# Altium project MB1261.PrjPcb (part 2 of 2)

## Sheet Peripherals.SchDoc: Peripherals
size A4; Author: P.A.; CompanyName: STMicroelectronics; Organization: Microcontrollers Division; Address1: 12, Rue Jules HOROWITZ; Address2: 38019 Grenoble; Address3: FRANCE; DocumentNumber: MB1261; Revision: B.01; SheetNumber: 7; SheetTotal: 15; Project: STM32L496G-DISCO
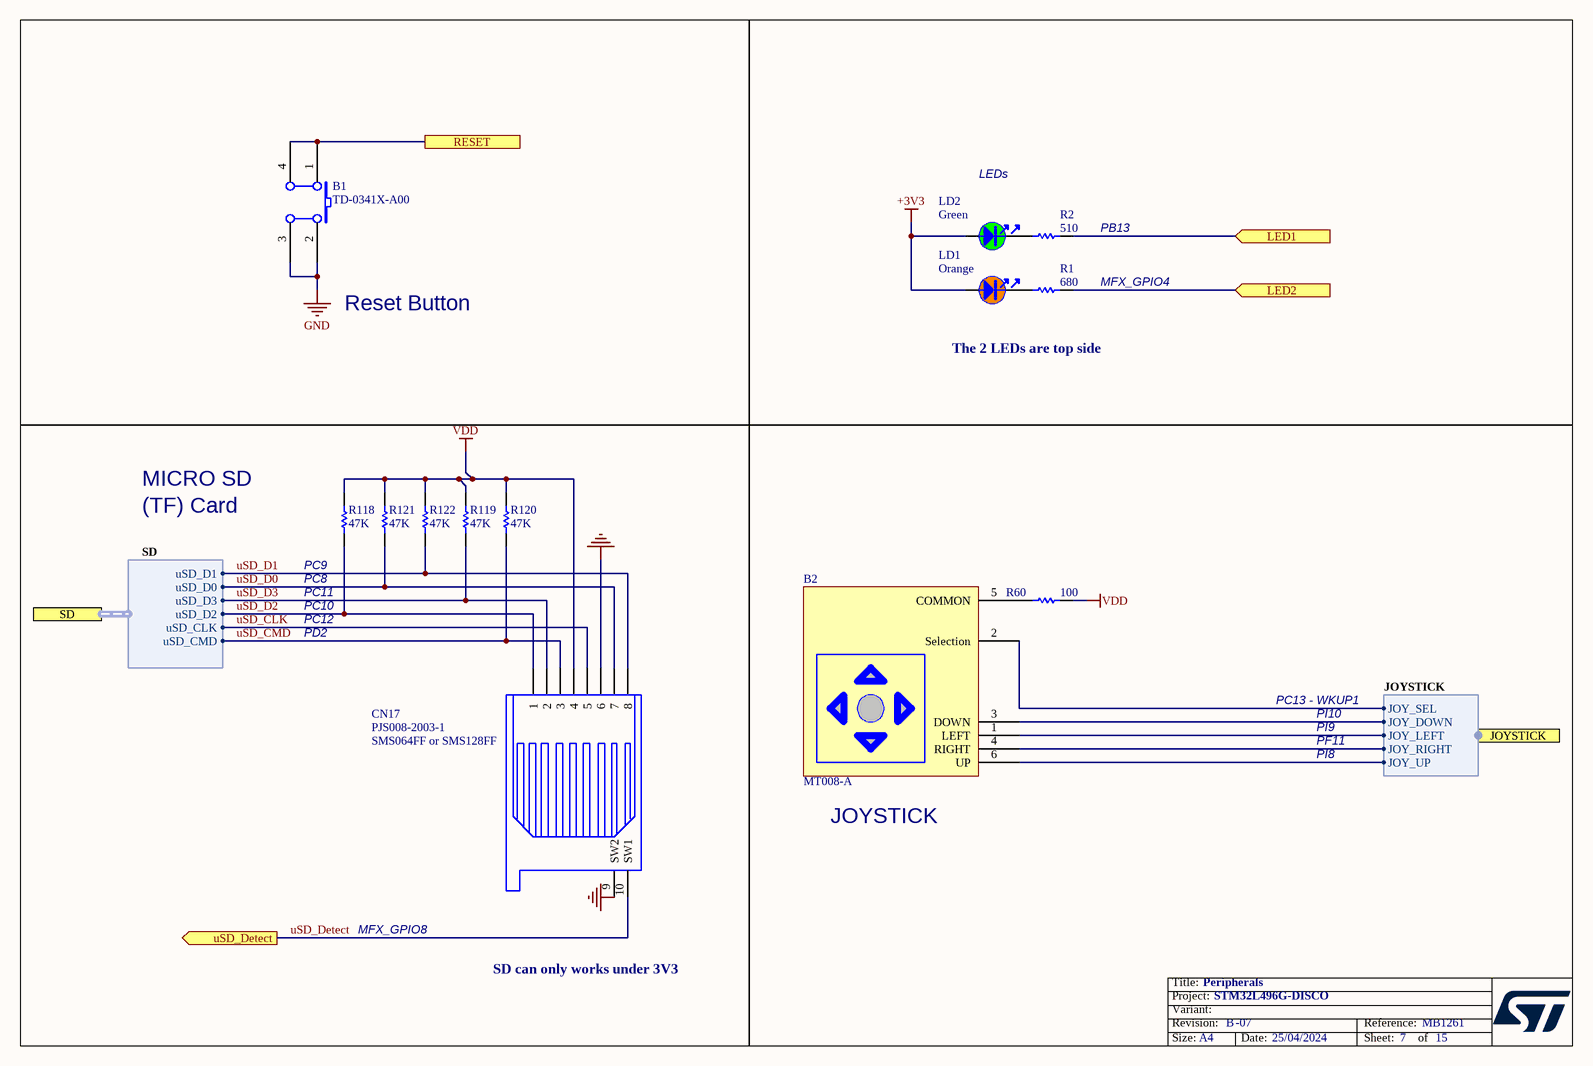
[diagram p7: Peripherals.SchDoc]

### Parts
B1  TD-0341X-A00  [PB10]
B2  MT008-A  [MT-008A]
CN17  PJS008-2003-1  [MSD_PJS008_]
LD1  value Orange  [LED_0603_ORANGE_H0P4]  (hidden comment: 19-217/S2C-AM2N2VY/3T)
LD2  value Green  [LED_0603_OSRAM_LG-Q396-PS-35_GREEN_1A2K_H0P4]  (hidden comment: LED_green)
R1  value 680  [0603R]  (hidden comment: RC0603FR-07680RL)
R2  value 510  [0603R]  (hidden comment: RC0603FR-07510RL)
R60  value 100  [0603R]  (hidden comment: RC0603JR-07100RL)
R118  47K  [0603R]
R119  47K  [0603R]
R120  47K  [0603R]
R121  47K  [0603R]
R122  47K  [0603R]

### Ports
JOYSTICK (harness JOYSTICK), LED1 (in), LED2 (in), RESET, SD (harness SD), uSD_Detect (out)

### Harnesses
SD: uSD_D0, uSD_CLK, uSD_D1, uSD_D2, uSD_D3, uSD_CMD
JOYSTICK: JOY_SEL, JOY_DOWN, JOY_LEFT, JOY_RIGHT, JOY_UP

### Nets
+3V3: LD1.1 LD2.1  [project net 3V3_OUT]
GND: B1.2(B0) B1.3(B1) CN17.6 CN17.9(SW2)
VDD: CN17.4 R60.1 R118.2 R119.2 R120.2 R121.2 R122.2
JOY_DOWN: B2.3(DOWN) ; port JOYSTICK.JOY_DOWN
JOY_LEFT: B2.1(LEFT) ; port JOYSTICK.JOY_LEFT
JOY_RIGHT: B2.4(RIGHT) ; port JOYSTICK.JOY_RIGHT
JOY_SEL: B2.2(Selection) ; port JOYSTICK.JOY_SEL
JOY_UP: B2.6(UP) ; port JOYSTICK.JOY_UP
LED1: R2.1 ; port LED1
NRST: B1.1(A0) B1.4(A1) ; port RESET
uSD_CLK: CN17.5 ; port SD.uSD_CLK
uSD_CMD: CN17.3 R120.1 ; port SD.uSD_CMD
uSD_D0: CN17.7 R121.1 ; port SD.uSD_D0
uSD_D1: CN17.8 R122.1 ; port SD.uSD_D1
uSD_D2: CN17.1 R118.1 ; port SD.uSD_D2
uSD_D3: CN17.2 R119.1 ; port SD.uSD_D3
uSD_Detect: CN17.10(SW1) ; port uSD_Detect
NetB2_5: B2.5(COMMON) R60.2
NetLD1_2: LD1.2 R1.2
NetLD2_2: LD2.2 R2.2
NetR1_1: R1.1 ; port LED2

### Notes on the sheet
- LEDs
- (near R2) PB13
- Reset Button
- MFX_GPIO4
- The 2 LEDs are top side
- MICRO SD
- (TF) Card
- (near R118) PC8
- (near R118) PC9
- PC11
- PC10
- PC12
- PD2
- PC13 - WKUP1
- PI9
- PI10
- (near CN17) SMS064FF or SMS128FF
- PF11
- PI8
- JOYSTICK
- MFX_GPIO8
- SD can only works under 3V3

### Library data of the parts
B1 = SW PUSHBUTTON: SE Push Button TD-0341 [RESET/Black]; Manuf_1: Chau-hua; Manuf_Part_1: CTSM-644N-V-T/R; Manuf_2: wealthmetal; Ordered by: Subcon; Assembly: with Back cap; Silkscreen: RESET; ECCN_US/EU: NA
B2 = MT-008A: Joystick; Manuf_1: XIEJIA; Ordered by: Subcon; Assembly: with button; ECCN_US/EU: NA
CN17 = SMS016AFA5E: Manuf_1: Yamaichi; Ordered by: Subcon; Silkscreen: uSD; ECCN_US/EU: NA
LD1 = MCD-02785: LED, Orange, 2V2, 5mA, 0603; Part_Type: Display; Part_Preference: Recommended; Manufacturer: EVERLIGHT; Manufacturer_Part_Number: 19-217/S2C-AM2N2VY/6T; Full_Alternate_Internal_Part_Number: MCD-00321; Component_Country_Of_Origin: China; ShowFields: YES; ID: 4897
LD2 = MCD-02901: LED, Green, 2V, 20mA, 0603; Part_Type: Display; Part_Preference: Recommended; Manufacturer: EVERLIGHT; Manufacturer_Part_Number: 19-217/G7C-AN1P2/6T; Partial_Alternate_Internal_Part_Number: MCD-02400; Component_Country_Of_Origin: China; ShowFields: YES; ID: 5017
R1 = res1: Resistor,680R,0603,1%,YAGEO; Ordered by: Subcon; ECCN_US/EU: NA
R2 = res1: Resistor,510R,0603,1%,YAGEO; Ordered by: Subcon; ECCN_US/EU: NA
R60 = res1: Resistor, 100 ,0603,1%,YAGEO; Ordered by: Subcon; ECCN_US/EU: NA
R118-R122 = res1: Resistor,47K,0603,1%,YAGEO; Manuf_Part_1: RC0603FR-0747KL; Ordered by: Subcon; ECCN_US/EU: NA

## Sheet Power.SchDoc: Power
size A4; Author: P.A.; CompanyName: STMicroelectronics; Organization: Microcontrollers Division; Address1: 12, Rue Jules HOROWITZ; Address2: 38019 Grenoble; Address3: FRANCE; DocumentNumber: MB1261; Revision: B.01; SheetNumber: 3; SheetTotal: 15; Project: STM32L496G-DISCO
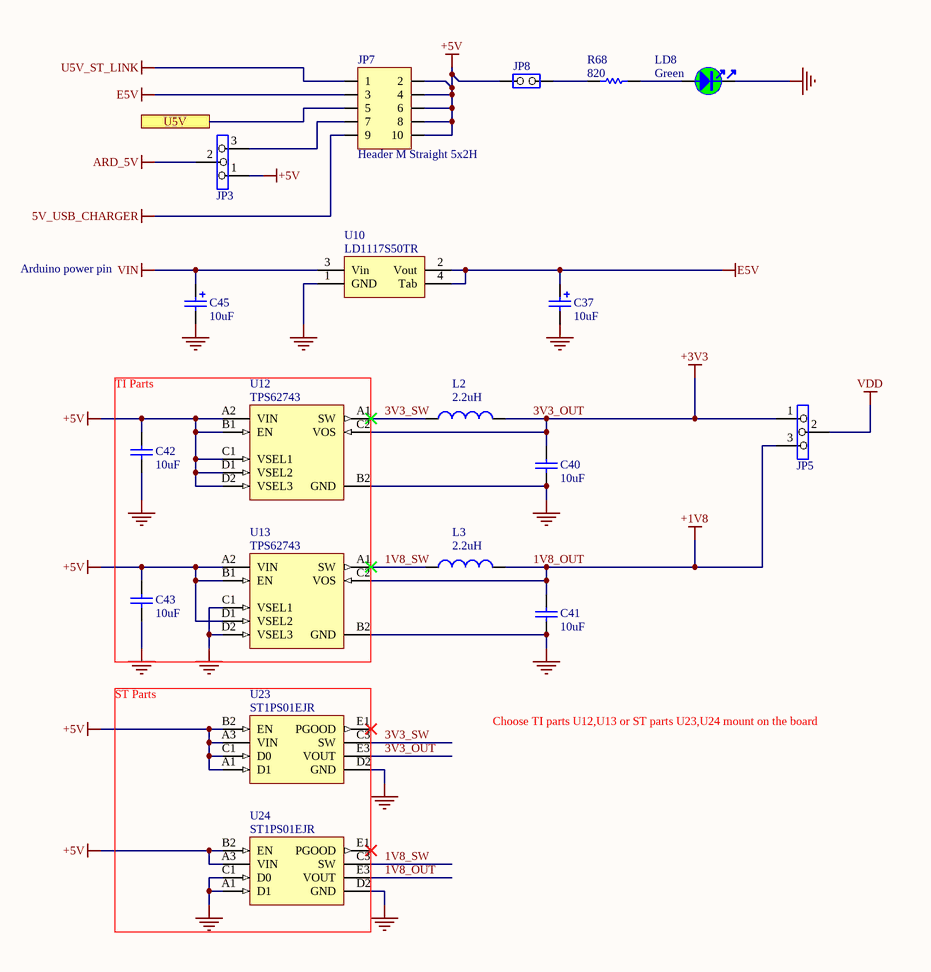
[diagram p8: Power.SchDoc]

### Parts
C37  value 10uF  [TAN-A]  (hidden comment: TAJA106K016R)
C40  value 10uF  [C0402]  (hidden comment: GRM155R60J106ME11)
C41  value 10uF  [C0402]  (hidden comment: GRM155R60J106ME11)
C42  value 10uF  [C0402]  (hidden comment: GRM155R60J106ME11)
C43  value 10uF  [C0402]  (hidden comment: GRM155R60J106ME11)
C45  value 10uF  [TAN-B]  (hidden comment: TAJB106K025RNJ)
JP3  3 PIN Jumper  [SIP3]  (value not drawn)
JP5  3 PIN Jumper  [SIP3]  (value not drawn)
JP7  Header M Straight 5x2H  [HDR_2X5_2R54]
JP8  2 PIN Jumper  [SIP2]  (value not drawn)
L2  2.2uH  [L1008_L0805_CPT]
L3  2.2uH  [L1008_L0805_CPT]
LD8  value Green  [LED_0603_OSRAM_LG-Q396-PS-35_GREEN_1A2K_H0P4]  (hidden comment: 19-213SY6C/S530-E2/TR8LED)
R68  820  [0603R]
U10  LD1117S50TR  [SOT-223]
U12  TPS62743  [BGA8_0R4_0R9X1R6]
U13  TPS62743  [BGA8_0R4_0R9X1R6]
U23  ST1PS01EJR  [BGA8_0R312-0R25_1R11X1R41]
U24  ST1PS01EJR  [BGA8_0R312-0R25_1R11X1R41]

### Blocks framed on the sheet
TI Parts: C42 C43 U12 U13
ST Parts: U23 U24

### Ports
U5V

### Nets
1V8_OUT: C41.1 JP5.3 L3.2 U13.C2(VOS) U24.E3(VOUT)  [also labelled +1V8]
3V3_OUT: C40.1 JP5.1 L2.2 U12.C2(VOS) U23.E3(VOUT)  [also labelled +3V3]
5V_USB_CHARGER: JP7.9
+5V: C42.1 C43.1 JP3.1 JP7.2 JP7.4 JP7.6 JP7.8 JP7.10 JP8.1(COMMON) U12.A2(VIN) U12.B1(EN) U12.C1(VSEL1) U12.D1(VSEL2) U12.D2(VSEL3) U13.A2(VIN) U13.B1(EN) U13.D1(VSEL2) U23.A1(D1) U23.A3(VIN) U23.B2(EN) U23.C1(D0) U24.A3(VIN) U24.B2(EN)
ARD_5V: JP3.2
E5V: C37.1 JP7.3 U10.2(Vout) U10.4(Tab)
GND: C37.2 C40.2 C41.2 C42.2 C43.2 C45.2 LD8.2 U10.1(GND) U12.B2(GND) U13.B2(GND) U13.C1(VSEL1) U13.D2(VSEL3) U23.D2(GND) U24.A1(D1) U24.C1(D0) U24.D2(GND)
U5V_ST_LINK: JP7.1
VDD: JP5.2
VIN: C45.1 U10.3(Vin)
1V8_SW: L3.1 U13.A1(SW) U24.C3(SW)
3V3_SW: L2.1 U12.A1(SW) U23.C3(SW)
USB_OTGFS_VBUS: JP7.5 ; port U5V
NetJP3_3: JP3.3 JP7.7
NetJP8_2: JP8.2(NO) R68.2
NetLD8_1: LD8.1 R68.1

Not connected (* = marked no-connect by the designer): U23 E1(PGOOD)*; U24 E1(PGOOD)*

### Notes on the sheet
- Arduino power pin
- Choose TI parts U12,U13 or ST parts U23,U24 mount on the board

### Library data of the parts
C37 = Cap Pol1: TAN Capacitor,10uF,10%,16V,A Type,AVX; Ordered by: Subcon; ECCN_US/EU: NA
C40-C43 = MCD-01532: Capacitor, MLCC, 10uF, 10V, X5R, +/-20%, 0402, T=0.5mm; Part_Preference: Recommended; Manufacturer: MURATA; Manufacturer_Part_Number: GRM155R61A106ME11; Component_Country_Of_Origin: Japan°°; ShowFields: YES; ID: 3632
C45 = Cap Pol1: Tan Capacitor,10uF,10%,25V,Tan-B,TAJB106K025RNJ; Manuf_1: AVX; Ordered by: Subcon; ECCN_US/EU: NA
JP3 JP5 = Jumper3: Manuf_1: lyconn; Manuf_Part_1: 313103S111116; Ordered by: Subcon; Silkscreen: +3V3: pins 1&2 +1V8: pins 2&3; ECCN_US/EU: NA
JP7 = Header 5X2M: Pin Header male,2.54mm,2*5,L=11.6,180,1U,DIP; Manuf_1: Lyconn; Ordered by: Subcon
JP8 = JP2: Manuf_1: lyconn; Manuf_Part_1: 313102S111116; Ordered by: Subcon; Assembly: with jumper; ECCN_US/EU: NA
L2 L3 = Inductor: Manuf_1: TDK; Manuf_Part_1: VLS252010HBX-2R2M-1; Ordered by: Subcon; ECCN_US/EU: NA
LD8 = MCD-02901: as LD2 on sheet Peripherals
R68 = res1: Resistor; Manuf_1: YAGEO; Manuf_Part_1: RC0603FR-07820RL; Ordered by: Subcon; ECCN_US/EU: NA
U10 = LD1117S18TR: Adjustable and fixed low drop positive voltage regulator; Ordered by: STM
U12 U13 = TPS62743: High Efficiency Buck Converter; Manuf_1: TI; Ordered by: Subcon
U23 = ST1PS01EJR: 400mA NanoQuiescent Step Down converter; Manuf_1: STM
U24 = ST1PS01EJR: 400mA NanoQuiescent Step Down converter; Ordered by: STM

## Sheet PSRAM.SchDoc: PSRAM
size A4; Author: P.A.; CompanyName: STMicroelectronics; Organization: Microcontrollers Division; Address1: 12, Rue Jules HOROWITZ; Address2: 38019 Grenoble; Address3: FRANCE; DocumentNumber: MB1261; Revision: B.01; SheetNumber: 12; SheetTotal: 15; Project: STM32L496G-DISCO
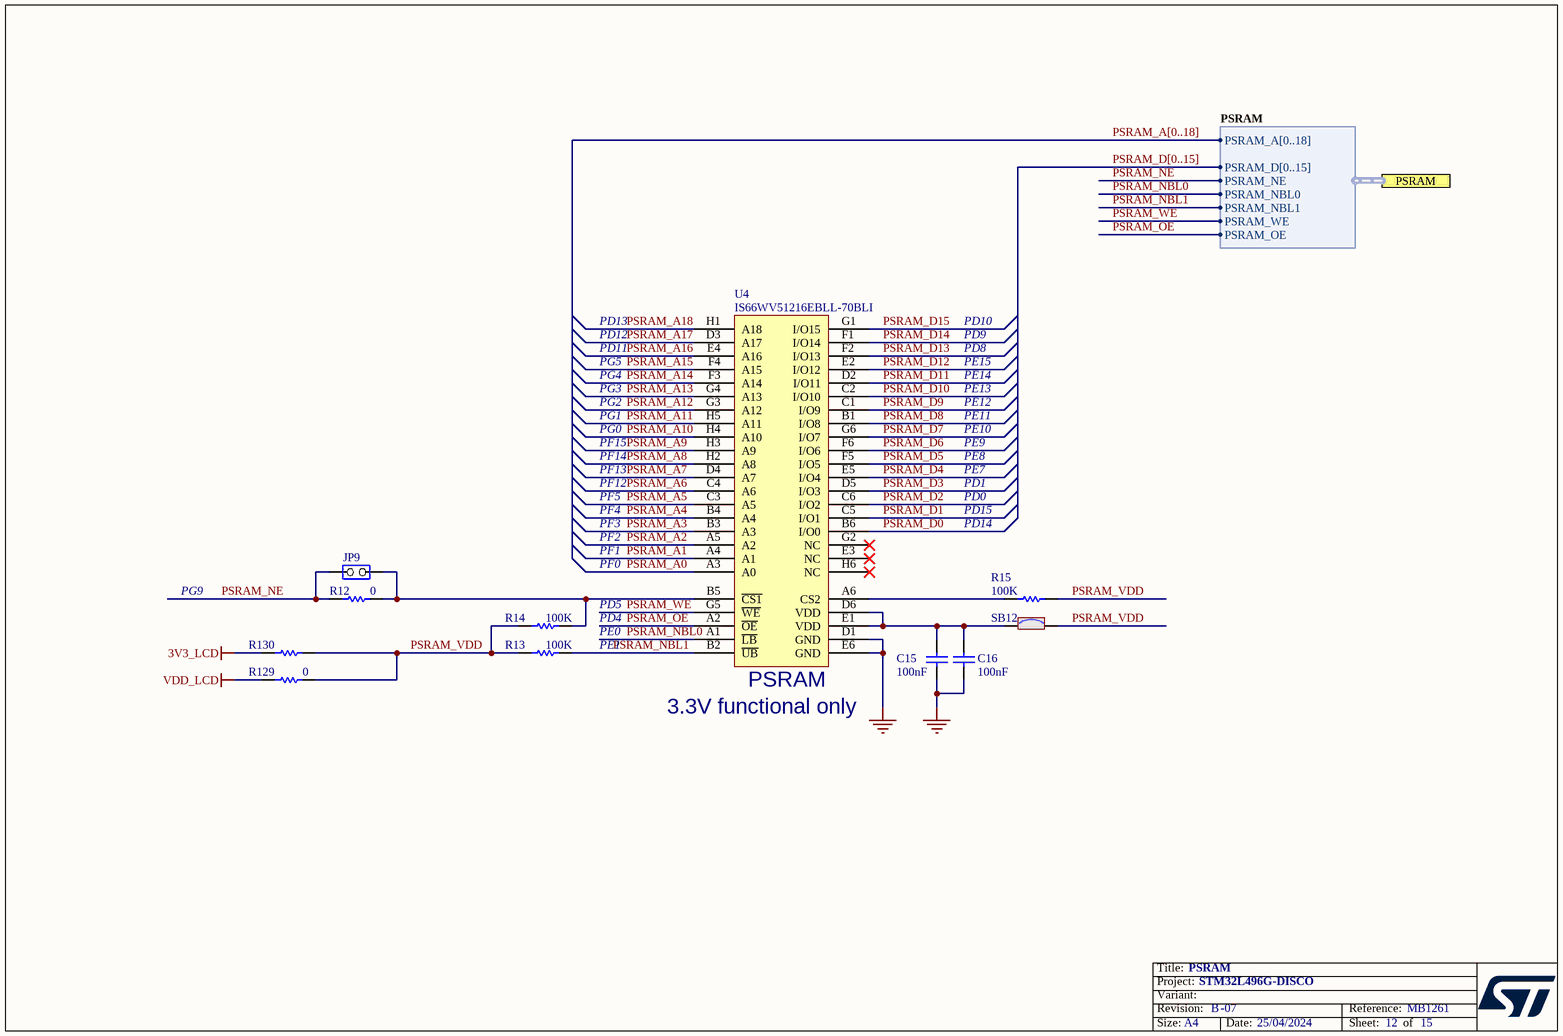
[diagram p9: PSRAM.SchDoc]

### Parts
C15  value 100nF  [0603C]  (hidden comment: CC0603KRX7R7BB104)
C16  value 100nF  [0603C]  (hidden comment: CC0603KRX7R7BB104)
JP9  2 PIN Jumper  [SIP2]  (value not drawn)
R12  0  [0603R]
R13  value 100K  [0603R]  (hidden comment: RC0603FR-07100KL)
R14  value 100K  [0603R]  (hidden comment: RC0603FR-07100KL)
R15  value 100K  [0603R]  (hidden comment: RC0603FR-07100KL)
R129  value 0  [0603R]  (hidden comment: RC0603JR-070RL)
R130  (no value)  [0603R]
SB12  Solder Bridge ON  [SB_0603]  (value not drawn)
U4  IS66WV51216EBLL-70BLI  [FBGA48_0R75_6X8]

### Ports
PSRAM (harness PSRAM)

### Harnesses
PSRAM: PSRAM_A[0..18], PSRAM_NE, PSRAM_NBL0, PSRAM_WE, PSRAM_OE, PSRAM_D[0..15], PSRAM_NBL1

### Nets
3V3_LCD: R130.2
GND: C15.2 C16.2 U4.D1(GND) U4.E6(GND)
VDD_LCD: R129.2
PSRAM_A0: U4.A3(A0)
PSRAM_A1: U4.A4(A1)
PSRAM_A2: U4.A5(A2)
PSRAM_A3: U4.B3(A3)
PSRAM_A4: U4.B4(A4)
PSRAM_A5: U4.C3(A5)
PSRAM_A6: U4.C4(A6)
PSRAM_A7: U4.D4(A7)
PSRAM_A8: U4.H2(A8)
PSRAM_A9: U4.H3(A9)
PSRAM_A10: U4.H4(A10)
PSRAM_A11: U4.H5(A11)
PSRAM_A12: U4.G3(A12)
PSRAM_A13: U4.G4(A13)
PSRAM_A14: U4.F3(A14)
PSRAM_A15: U4.F4(A15)
PSRAM_A16: U4.E4(A16)
PSRAM_A17: U4.D3(A17)
PSRAM_A18: U4.H1(A18)  [project net LCD_RS]
PSRAM_D0: U4.B6(I/O0)  [project net D0]
PSRAM_D1: U4.C5(I/O1)  [project net D1]
PSRAM_D2: U4.C6(I/O2)  [project net D2]
PSRAM_D3: U4.D5(I/O3)  [project net D3]
PSRAM_D4: U4.E5(I/O4)  [project net D4]
PSRAM_D5: U4.F5(I/O5)  [project net D5]
PSRAM_D6: U4.F6(I/O6)  [project net D6]
PSRAM_D7: U4.G6(I/O7)  [project net D7]
PSRAM_D8: U4.B1(I/O8)  [project net D8]
PSRAM_D9: U4.C1(I/O9)  [project net D9]
PSRAM_D10: U4.C2(I/O10)  [project net D10]
PSRAM_D11: U4.D2(I/O11)  [project net D11]
PSRAM_D12: U4.E2(I/O12)  [project net D12]
PSRAM_D13: U4.F2(I/O13)  [project net D13]
PSRAM_D14: U4.F1(I/O14)  [project net D14]
PSRAM_D15: U4.G1(I/O15)  [project net D15]
PSRAM_NBL0: U4.A1(~{LB}) ; port PSRAM.PSRAM_NBL0
PSRAM_NBL1: R13.1 U4.B2(~{UB}) ; port PSRAM.PSRAM_NBL1
PSRAM_NE: JP9.1(COMMON) R12.2 ; port PSRAM.PSRAM_NE
PSRAM_OE: U4.A2(~{OE}) ; port PSRAM.PSRAM_OE  [project net LCD_OE]
PSRAM_VDD: R13.2 R14.2 R15.1 R129.1 R130.1 SB12.2
PSRAM_WE: U4.G5(~{WE}) ; port PSRAM.PSRAM_WE  [project net LCD_WE]
NetC15_1: C15.1 C16.1 SB12.1 U4.D6(VDD) U4.E1(VDD)
NetJP9_2: JP9.2(NO) R12.1 R14.1 U4.B5(~{CS1})
NetR15_2: R15.2 U4.A6(CS2)

Not connected (* = marked no-connect by the designer): U4 E3(NC)* G2(NC)* H6(NC)*

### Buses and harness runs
bus PSRAM_A[0..18]
bus PSRAM_D[0..15]

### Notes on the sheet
- PD11
- PD12
- PD13
- PG4
- PG5
- PE14
- PE15
- PD8
- PD9
- PD10
- PF15
- PG0
- PG1
- PG2
- PG3
- PE9
- PE10
- PE11
- PE12
- PE13
- PF4
- PF5
- PF12
- PF13
- PF14
- PD15
- PD0
- PD1
- PE7
- PE8
- PF0
- PF1
- PF2
- PF3
- PD14
- PG9
- PD5
- PD4
- PE0
- PE1
- 3.3V functional only
- (near U4) PSRAM

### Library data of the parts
C15 C16 = Cap: Capacitor,100nF,10%,16V,X7R,0603,YAGEO; Ordered by: Subcon
JP9 = JP2: as JP8 on sheet Power
R12 = res1: Resistor, 0 ,0603,1%,YAGEO; Manuf_Part_1: RC0603JR-070RL; Ordered by: Subcon; ECCN_US/EU: NA
R13-R15 = res1: Resistor,100K,0603,1%,YAGEO; Ordered by: Subcon; ECCN_US/EU: NA
R129 = res1: Resistor, 0 ,0603,1%,YAGEO; Ordered by: Subcon; ECCN_US/EU: NA
R130 = res1: Resistor, 0 ,0603,1%,YAGEO; Manuf_Part_1: RC0603JR-070RL; Value: 0; Ordered by: Subcon; ECCN_US/EU: NA
SB12 = SB_ON: Manuf_1: YAGEO; Manuf_Part_1: RC0603JR-070RL; Solder: YES; Ordered By: Subcon
U4 = IS66WV51216EBLL-70BLI: 8M Bit static RAMs organized as 512K words by  16 bits.; Manuf_1: ISSI; Ordered by: STM

## Sheet QSPI.SchDoc: QSPI Flash
size A4; Author: P.A.; CompanyName: STMicroelectronics; Organization: Microcontrollers Division; Address1: 12, Rue Jules HOROWITZ; Address2: 38019 Grenoble; Address3: FRANCE; DocumentNumber: MB1261; Revision: B.01; SheetNumber: 6; SheetTotal: 15; Project: STM32L496G-DISCO
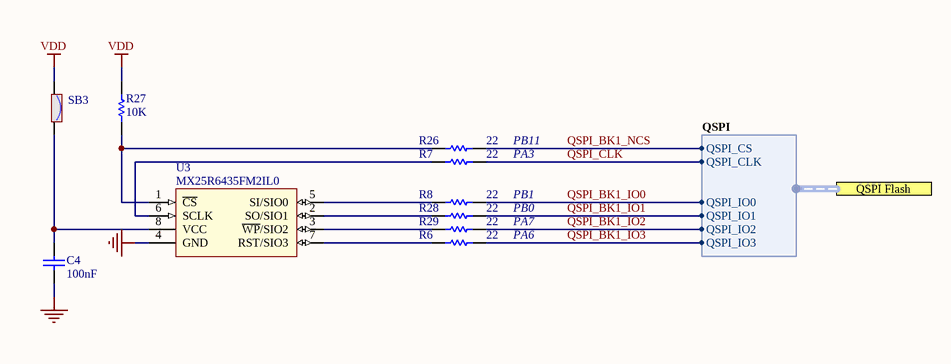
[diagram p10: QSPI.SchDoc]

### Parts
C4  value 100nF  [0603C]  (hidden comment: CC0603KRX7R7BB104)
R6  value 22  [0603R]  (hidden comment: RC0603JR-0722RL)
R7  value 22  [0603R]  (hidden comment: RC0603JR-0722RL)
R8  value 22  [0603R]  (hidden comment: RC0603JR-0722RL)
R26  value 22  [0603R]  (hidden comment: RC0603JR-0722RL)
R27  value 10K  [0603R]  (hidden comment: RC0603FR-0710KL)
R28  value 22  [0603R]  (hidden comment: RC0603JR-0722RL)
R29  value 22  [0603R]  (hidden comment: RC0603JR-0722RL)
SB3  Solder Bridge ON  [SB_0603]  (value not drawn)
U3  MX25R6435FM2IL0  [SOIC8_1R27_5R28X7R9]

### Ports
QSPI Flash (harness QSPI)

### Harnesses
QSPI: QSPI_IO1, QSPI_IO0, QSPI_CLK, QSPI_CS, QSPI_IO2, QSPI_IO3

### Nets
GND: C4.2 U3.4(GND)
VDD: R27.2 SB3.1
QSPI_BK1_IO0: R8.1 ; port QSPI Flash.QSPI_IO0
QSPI_BK1_IO1: R28.1 ; port QSPI Flash.QSPI_IO1
QSPI_BK1_IO2: R29.1 ; port QSPI Flash.QSPI_IO2
QSPI_BK1_IO3: R6.1 ; port QSPI Flash.QSPI_IO3
QSPI_BK1_NCS: R26.1 ; port QSPI Flash.QSPI_CS
QSPI_CLK: R7.1 ; port QSPI Flash.QSPI_CLK
NetC4_1: C4.1 SB3.2 U3.8(VCC)
NetR6_2: R6.2 U3.7(RST/SIO3)
NetR7_2: R7.2 U3.6(SCLK)
NetR8_2: R8.2 U3.5(SI/SIO0)
NetR26_2: R26.2 R27.1 U3.1(~{CS})
NetR28_2: R28.2 U3.2(SO/SIO1)
NetR29_2: R29.2 U3.3(~{WP}/SIO2)

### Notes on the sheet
- PB11
- PA3
- PB0
- PB1
- PA6
- PA7

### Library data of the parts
C4 = Cap: as C15 on sheet PSRAM
R6-R8 R26 R28 R29 = res1: Resistor, 22 ,0603,1%,YAGEO; Ordered by: Subcon; ECCN_US/EU: NA
R27 = res1: Resistor,10K,0603,1%,YAGEO; Ordered by: Subcon; ECCN_US/EU: NA
SB3 = SB_ON: as SB12 on sheet PSRAM
U3 = MX25R6435FM2IL0: Ultra Low Power 64M-BIT CMOS MXSMIO FLASH MEMORY; Manuf_1: MXIC; Ordered by: Subcon

## Sheet ST_LINK_V2-1_2.SCHDOC: ST-LINK/V2-1
size A3; Author: P.A.; CompanyName: STMicroelectronics; Organization: Microcontrollers Division; Address1: 12, Rue Jules HOROWITZ; Address2: 38019 Grenoble; Address3: FRANCE; DocumentNumber: MB1261; Revision: B.01; SheetNumber: 5; SheetTotal: 15; Project: STM32L496G-DISCO
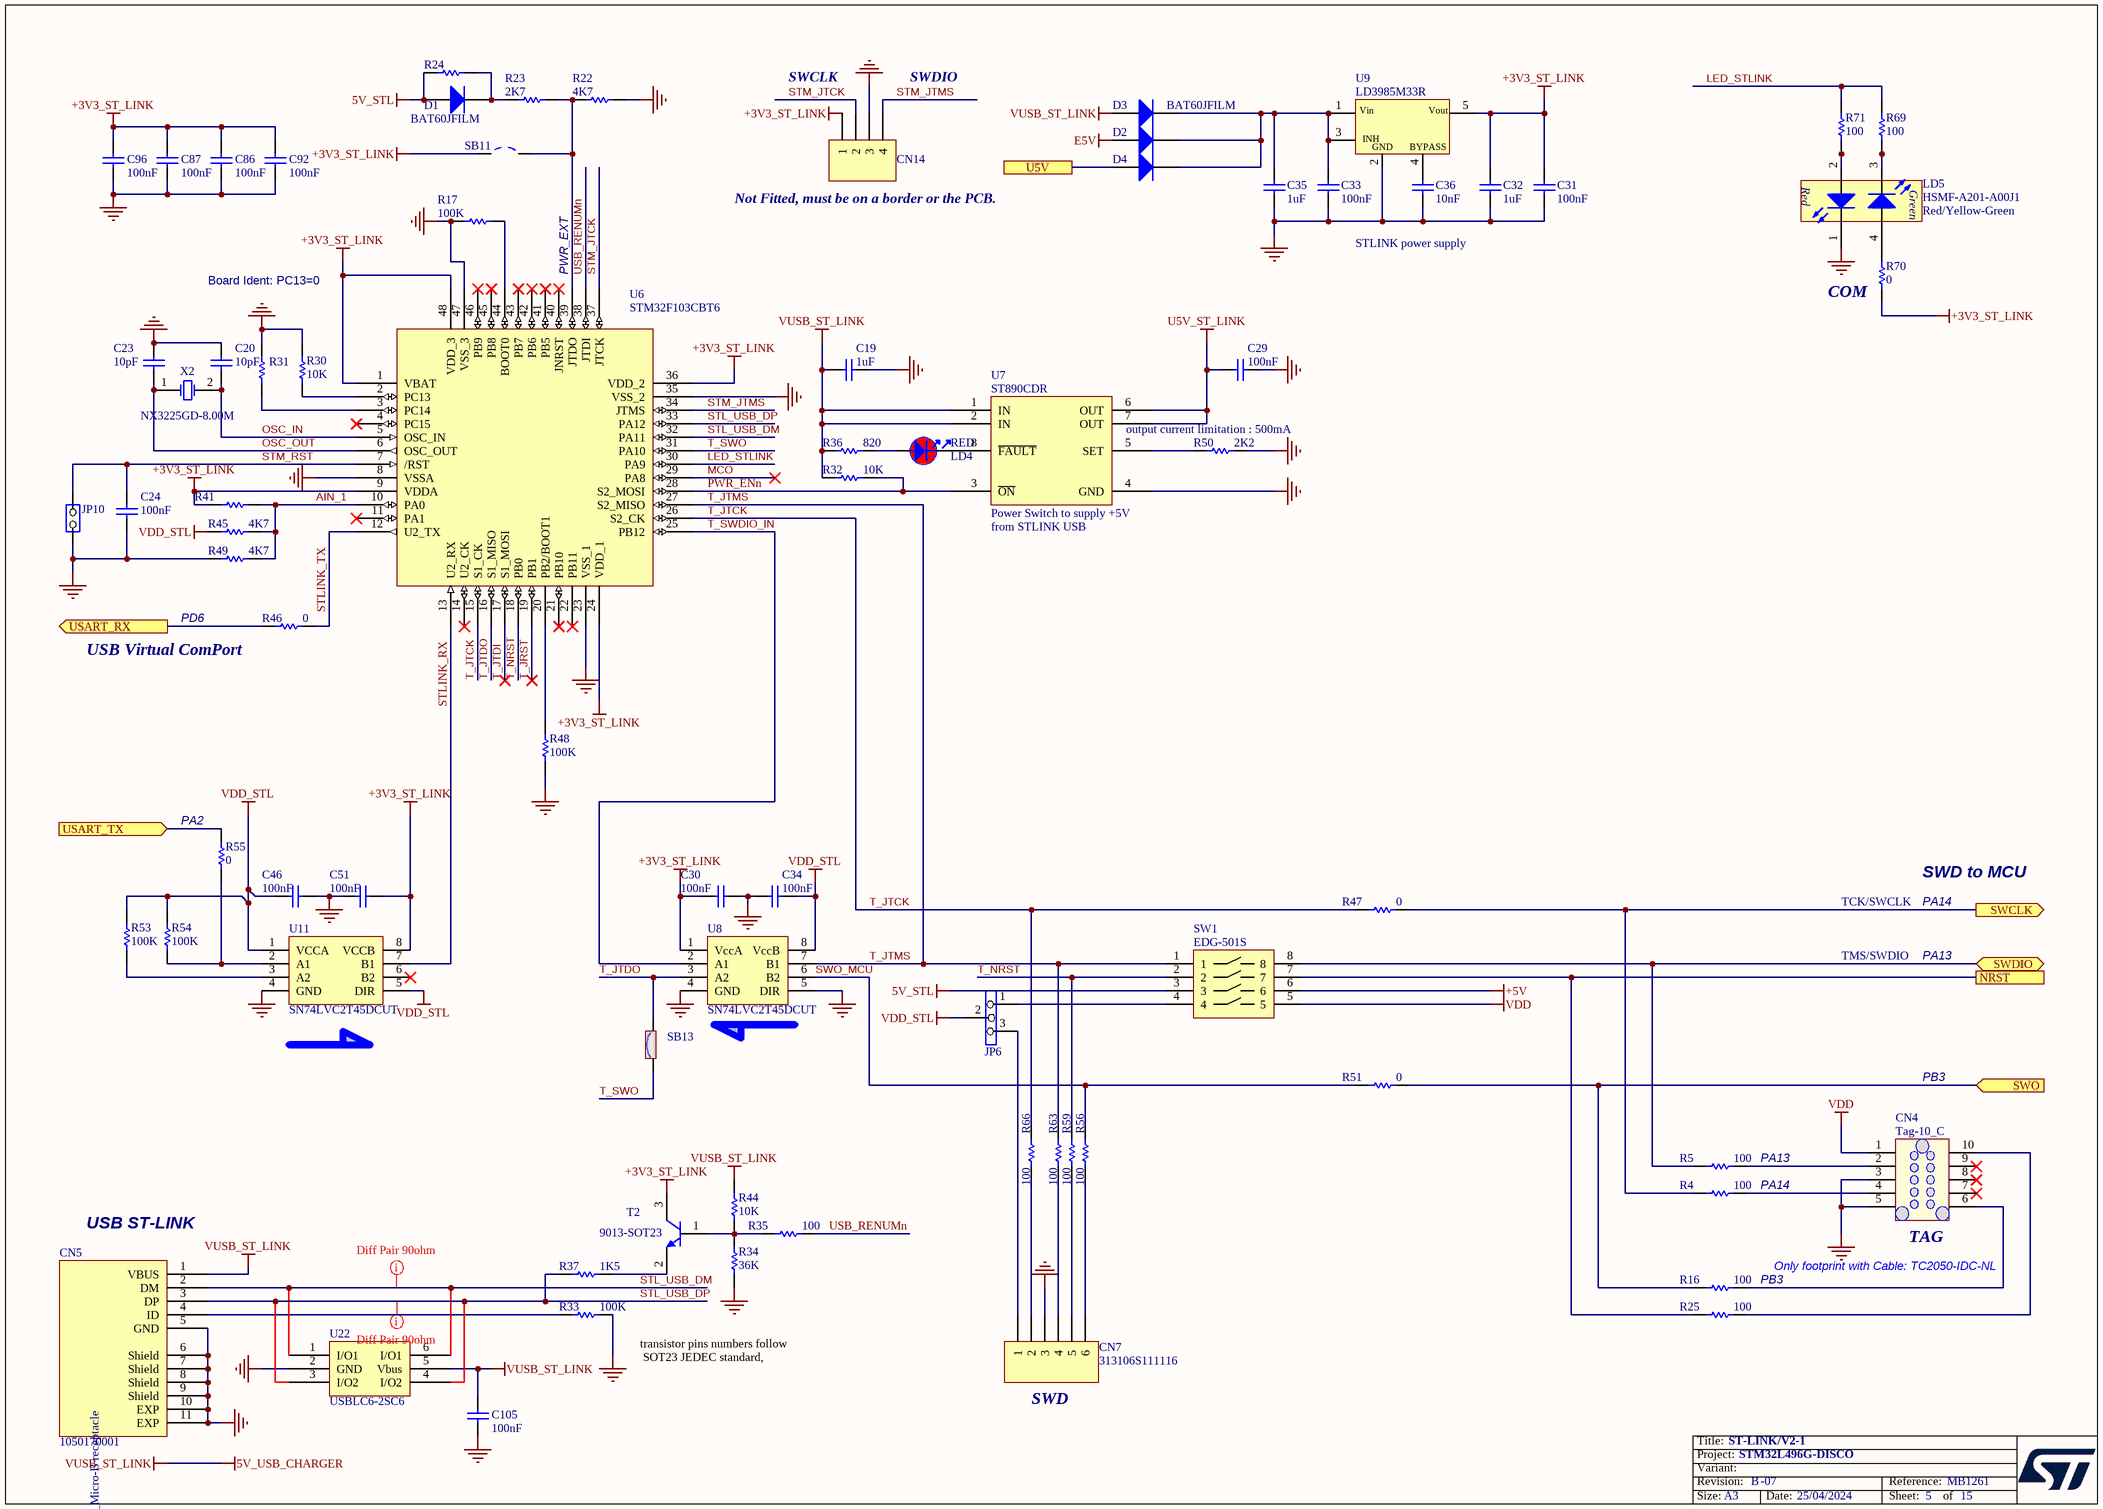
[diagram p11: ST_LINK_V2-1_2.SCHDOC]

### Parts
C19  value 1uF  [0603C]  (hidden comment: CC0603KRX5R7BB105)
C20  value 10pF  [0603C]  (hidden comment: CC0603JRNPO9BN100)
C23  value 10pF  [0603C]  (hidden comment: CC0603JRNPO9BN100)
C24  value 100nF  [0603C]  (hidden comment: CC0603KRX7R7BB104)
C29  value 100nF  [0603C]  (hidden comment: CC0603KRX7R7BB104)
C30  value 100nF  [0603C]  (hidden comment: CC0603KRX7R7BB104)
C31  value 100nF  [0603C]  (hidden comment: CC0603KRX7R7BB104)
C32  value 1uF  [0603C]  (hidden comment: CC0603KRX5R7BB105)
C33  value 100nF  [0603C]  (hidden comment: CC0603KRX7R7BB104)
C34  value 100nF  [0603C]  (hidden comment: CC0603KRX7R7BB104)
C35  value 1uF  [0603C]  (hidden comment: CC0603KRX5R7BB105)
C36  value 10nF  [C0603]  (hidden comment: CC0603KRX7R9BB103)
C46  value 100nF  [0603C]  (hidden comment: CC0603KRX7R7BB104)
C51  value 100nF  [0603C]  (hidden comment: CC0603KRX7R7BB104)
C86  value 100nF  [0603C]  (hidden comment: CC0603KRX7R7BB104)
C87  value 100nF  [0603C]  (hidden comment: CC0603KRX7R7BB104)
C92  value 100nF  [0603C]  (hidden comment: CC0603KRX7R7BB104)
C96  value 100nF  [0603C]  (hidden comment: CC0603KRX7R7BB104)
C105  value 100nF  [0603C]  (hidden comment: CC0603KRX7R7BB104)
CN4  Tag-10_C  [TC2050-IDC-NL]
CN5  1050170001  [MICRO_USB_B_105017]
CN7  313106S111116  [HDR_1X6_2R54_W]
CN14  (no value)  [HDR_1X4_2R54]
D1  BAT60JFILM  [SOD-323]
D2  (no value)  [SOD-323]
D3  BAT60JFILM  [SOD-323]
D4  (no value)  [SOD-323]
JP6  3 PIN Jumper  [SIP3]  (value not drawn)
JP10  (no value)  [SIP2]
LD4  value RED  [LED_0603_VISHAY_VLMS1300-GS08_RED_1A2K_H0P8]  (hidden comment: 19-217/R6C-AL1M2VY/3T)
LD5  HSMF-A201-A00J1  value Red/Yellow-Green  [LED_BI-GR_HSMF-A201-A00J1]
R4  value 100  [0603R]  (hidden comment: RC0603JR-07100RL)
R5  value 100  [0603R]  (hidden comment: RC0603JR-07100RL)
R16  value 100  [0603R]  (hidden comment: RC0603JR-07100RL)
R17  value 100K  [0603R]  (hidden comment: RC0603FR-07100KL)
R22  value 4K7  [0603R]  (hidden comment: RC0603FR-074K7L)
R23  value 2K7  [0603R]  (hidden comment: RC0603FR-072K7L)
R24  (no value)  [0603R]
R25  value 100  [0603R]  (hidden comment: RC0603JR-07100RL)
R30  value 10K  [0603R]  (hidden comment: RC0603FR-0710KL)
R31  (no value)  [0603R]
R32  value 10K  [0603R]  (hidden comment: RC0603FR-0710KL)
R33  value 100K  [0603R]  (hidden comment: RC0603FR-07100KL)
R34  value 36K  [0603R]  (hidden comment: RC0603FR-0736KL)
R35  value 100  [0603R]  (hidden comment: RC0603JR-07100RL)
R36  820  [0603R]
R37  value 1K5  [0603R]  (hidden comment: RC0603FR-071K5L)
R41  (no value)  [0603R]
R44  value 10K  [0603R]  (hidden comment: RC0603FR-0710KL)
R45  value 4K7  [0603R]  (hidden comment: RC0603FR-074K7L)
R46  value 0  [0603R]  (hidden comment: RC0603JR-070RL)
R47  value 0  [0603R]  (hidden comment: RC0603JR-070RL)
R48  value 100K  [0603R]  (hidden comment: RC0603FR-07100KL)
R49  value 4K7  [0603R]  (hidden comment: RC0603FR-074K7L)
R50  value 2K2  [0603R]  (hidden comment: RC0603FR-072K2L)
R51  value 0  [0603R]  (hidden comment: RC0603JR-070RL)
R53  value 100K  [0603R]  (hidden comment: RC0603FR-07100KL)
R54  value 100K  [0603R]  (hidden comment: RC0603FR-07100KL)
R55  value 0  [0603R]  (hidden comment: RC0603JR-070RL)
R56  value 100  [0603R]  (hidden comment: RC0603JR-07100RL)
R59  value 100  [0603R]  (hidden comment: RC0603JR-07100RL)
R63  value 100  [0603R]  (hidden comment: RC0603JR-07100RL)
R66  value 100  [0603R]  (hidden comment: RC0603JR-07100RL)
R69  value 100  [0603R]  (hidden comment: RC0603JR-07100RL)
R70  value 0  [0603R]  (hidden comment: RC0603JR-070RL)
R71  value 100  [0603R]  (hidden comment: RC0603JR-07100RL)
SB11  Solder Bridge OFF  [SB_0603]  (value not drawn)
SB13  Solder Bridge ON  [SB_0603]  (value not drawn)
SW1  EDG-501S  [SW1_11R7X9R7-12R2X9R65-HDR_CPT]
T2  9013-SOT23  [SOT-23]
U6  STM32F103CBT6  [LQFP48_0R5_9X9]
U7  ST890CDR  [SOIC8_1R27_4R9X6]
U8  SN74LVC2T45DCUT  [USOP8_0R5_2X3R1]
U9  LD3985M33R  [SOT23-5]
U11  SN74LVC2T45DCUT  [USOP8_0R5_2X3R1]
U22  USBLC6-2SC6  [SOT23-6L]
X2  NX3225GD-8.00M  [XTAL_2SM_3R2X2R5]

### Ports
NRST, SWCLK (out), SWDIO (bidir), SWO (in), U5V, USART_RX (out), USART_TX (in)

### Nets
5V_STL: D1.1(A) R24.2 SW1.3
5V_USB_CHARGER: C19.2 C105.1 CN5.1(VBUS) D3.1(A) R32.1 R36.2 R44.1 U7.1(IN) U7.2(IN) U22.5(Vbus)  [also labelled VUSB_ST_LINK]
+3V3_ST_LINK: C30.2 C31.1 C32.1 C51.2 C86.1 C87.1 C92.1 C96.1 CN14.1 R41.1 R70.1 SB11.1 T2.3(C) U6.1(VBAT) U6.9(VDDA) U6.24(VDD_1) U6.36(VDD_2) U6.48(VDD_3) U8.1(VccA) U9.5(Vout) U11.8(VCCB)
+5V: SW1.6
E5V: D2.1(A)
GND: C19.1 C20.1 C23.1 C24.2 C29.1 C30.1 C31.2 C32.2 C33.2 C34.2 C35.2 C36.2 C46.2 C51.1 C86.2 C87.2 C92.2 C96.2 C105.2 CN4.3 CN4.5 CN5.5(GND) CN5.6(Shield) CN5.7(Shield) CN5.8(Shield) CN5.9(Shield) CN5.10(EXP) CN5.11(EXP) CN7.3 CN14.3 JP10.2(NO) LD5.1(RED_cathode) R17.2 R22.1 R30.1 R31.1 R33.1 R34.2 R48.1 R49.2 R50.1 U6.8(VSSA) U6.23(VSS_1) U6.35(VSS_2) U6.47(VSS_3) U7.4(GND) U8.4(GND) U8.5(DIR) U9.2(GND) U11.4(GND) U22.2(GND)
U5V_ST_LINK: C29.2 U7.6(OUT) U7.7(OUT)
VDD: CN4.1 SW1.5
VDD_STL: C34.1 C46.1 JP6.2 R45.2 R53.2 R54.2 U8.8(VccB) U11.1(VCCA) U11.5(DIR)
AIN_1: R41.2 R45.1 R49.1 U6.10(PA0)
LED_STLINK: R69.1 R71.1 U6.30(PA9)
MCO: U6.29(PA8)
NRST: R25.2 SW1.7 ; port NRST
OSC_IN: C20.2 U6.5(OSC_IN) X2.2(OSC2)
OSC_OUT: C23.2 U6.6(OSC_OUT) X2.1(OSC1)
PWR_ENn: R32.2 U6.28(S2_MOSI) U7.3(~{ON})
STL_USB_DM: CN5.2(DM) U6.32(PA11) U22.1(I/O1) U22.6(I/O1)
STL_USB_DP: CN5.3(DP) R37.2 U6.33(PA12) U22.3(I/O2) U22.4(I/O2)
STLINK_RX: U6.13(U2_RX) U11.7(B1)
STLINK_TX: R46.1 U6.12(U2_TX)
STM_JTCK: CN14.2 U6.37(JTCK)
STM_JTMS: CN14.4 U6.34(JTMS)
STM_RST: C24.1 JP10.1(COMMON) U6.7(/RST)
SWCLK: R4.2 R47.1 ; port SWCLK
SWDIO: R5.2 SW1.8 ; port SWDIO
SWO: R16.2 R51.1 ; port SWO
SWO_MCU: R51.2 R56.2 U8.6(B2)
T_JRST: U6.19(PB1)
T_JTCK: R47.2 R66.2 U6.15(S1_CK) U6.26(S2_CK)
T_JTDI: U6.17(S1_MOSI)
T_JTDO: SB13.2 U6.16(S1_MISO) U8.3(A2)
T_JTMS: R63.2 SW1.1 U6.27(S2_MISO) U8.7(B1)
T_NRST: R59.2 SW1.2 U6.18(PB0)
T_SWDIO_IN: U6.25(PB12) U8.2(A1)
T_SWO: SB13.1 U6.31(PA10)
USART2_RX: R46.2 ; port USART_RX
USART2_TX: R55.1 ; port USART_TX
USB_OTGFS_VBUS: D4.1(A) ; port U5V
USB_RENUMn: R35.2 U6.38(JTDI)
NetC33_1: C33.1 C35.1 D2.2(K) D3.2(K) D4.2(K) U9.1(Vin) U9.3(CE)
NetC36_1: C36.1 U9.4(BYPASS)
NetCN4_2: CN4.2 R5.1
NetCN4_4: CN4.4 R4.1
NetCN4_6: CN4.6 R16.1
NetCN4_10: CN4.10 R25.1
NetCN5_4: CN5.4(ID) R33.2
NetCN7_1: CN7.1 JP6.3
NetCN7_2: CN7.2 R66.1
NetCN7_4: CN7.4 R63.1
NetCN7_5: CN7.5 R59.1
NetCN7_6: CN7.6 R56.1
NetD1_2: D1.2(K) R23.2 R24.1
NetJP6_1: JP6.1 SW1.4
NetLD4_1: LD4.1 R36.1
NetLD4_2: LD4.2 U7.8(~{FAULT})
NetLD5_2: LD5.2(Red_anode) R71.2
NetLD5_3: LD5.3(YellowGreen_cathode) R69.2
NetLD5_4: LD5.4(YellowGreen_anode) R70.2
NetR17_1: R17.1 U6.44(BOOT0)
NetR22_2: R22.2 R23.1 SB11.2 U6.39(JTDO)
NetR30_2: R30.2 U6.2(PC13)
NetR31_2: R31.2 U6.3(PC14)
NetR34_1: R34.1 R35.1 R44.2 T2.1(B)
NetR37_1: R37.1 T2.2(E)
NetR48_2: R48.2 U6.20(PB2/BOOT1)
NetR50_2: R50.2 U7.5(SET)
NetR53_1: R53.1 U11.3(A2)
NetR54_1: R54.1 R55.2 U11.2(A1)

Not connected (* = marked no-connect by the designer): CN4 7* 8* 9*; U6 4(PC15)* 11(PA1)* 14(U2_CK)* 21(PB10)* 22(PB11)* 40(JNRST)* 41(PB5)* 42(PB6)* 43(PB7)* 45(PB8)* 46(PB9)*; U11 6(B2)*

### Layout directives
mark named Diff Pair 90ohm: STL_USB_DM, STL_USB_DP

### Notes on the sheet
- SWCLK
- SWDIO
- (near CN14) Not Fitted, must be on a border or the PCB.
- Board Ident: PC13=0
- PWR_EXT
- STLINK power supply
- (near R70) COM
- output current limitation : 500mA
- (near U7) Power Switch to supply +5V from STLINK USB
- PD6
- (near R46) USB Virtual ComPort
- (near R55) PA2
- TCK/SWCLK
- SWD to MCU
- PA14
- TMS/SWDIO
- PA13
- PB3
- (near CN5) USB ST-LINK
- (near CN4) TAG
- Only footprint with Cable: TC2050-IDC-NL
- transistor pins numbers follow
  SOT23 JEDEC standard,
- (near CN7) SWD

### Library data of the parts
C19 C32 C35 = Cap: Capacitor,1uF,0603,16V,10%,X5R,YAGEO; Ordered by: Subcon
C20 C23 = Cap: Capacitor,10pF,5%,50V,NPO,0603,YAGEO; Ordered by: Subcon
C24 C29-C31 C33 C34 C46 C51 C86 C87 C92 C96 C105 = Cap: as C15 on sheet PSRAM
C36 = MCD-00017: Capacitor, MLCC, 10nF, 50V, X7R, +/-10%, 0603, T=0.8mm; Part_Preference: Recommended; Manufacturer: YAGEO; Order_Code_RS: 722236; Component_Country_Of_Origin: China; ShowFields: YES; ID: 2500
CN4 = Tag-10_C: Footprint for TC2050-IDC-430 plug of nails (TM) cable for MP430; Manuf_1: None
CN5 = 1050170001: Manuf_1: MOLEX; Silkscreen: USB; Ordered by: Subcon; ECCN_US/EU: NA
CN7 = Header 6: Header, 6-Pin; Manuf_1: lyconn; Ordered by: Subcon; Silkscreen: SWD; ECCN_US/EU: NA
CN14 = Header 4: Header, 4-Pin; ECCN_US/EU: [N/A]
D1-D4 = BAT60JFILM: Provided: STM; ECCN_US/EU: EAR99/NEC; Ref St: 9151097
JP6 = Jumper3: Manuf_1: lyconn; Manuf_Part_1: 313103S111116; Ordered by: Subcon
JP10 = JP2: as JP8 on sheet Power
LD4 = MCD-02787: LED, Red, 1V7 To 2V2, 5mA, 0603; Part_Type: Display; Part_Preference: Recommended; Manufacturer: EVERLIGHT; Manufacturer_Part_Number: 19-217/R6C-AL1M2VY/6T; Partial_Alternate_Internal_Part_Number: MCD-02401, MCD-00586; Component_Country_Of_Origin: China; ShowFields: YES; ID: 4899
LD5 = MCD-02402: LED Bicolor, Red/Yellow-Green , 2V, 20mA, 4-PLCC; Part_Type: Display; Part_Preference: Not recommended; Manufacturer: EVERLIGHT; Manufacturer_Part_Number: 67-22SURSYGC/S530-A2/TR8; Full_Alternate_Internal_Part_Number: MCD-00051, MCD-02631; ShowFields: YES; ID: 4508
R4 R5 R16 R25 R35 R56 R59 R63 R66 R69 R71 = res1: as R60 on sheet Peripherals
R17 R33 R48 R53 R54 = res1: as R13-R15 on sheet PSRAM
R22 R45 R49 = res1: Resistor,4.7K,0603,1%,YAGEO; Ordered by: Subcon; ECCN_US/EU: NA
R23 = res1: Resistor,2.7K,0603,1%,YAGEO; Ordered by: Subcon; ECCN_US/EU: NA
R24 = Res_0_5%_0402: Resistor,0,0603,5%,YAGEO; Manuf_Part_1: RC0603JR-070RL; Value: 0Ohm; ECCN_US/EU: [N/A]; Ordered by: Subcon
R30 R32 R44 = res1: as R27 on sheet QSPI
R31 R41 = res1: Resistor,100K,0603,1%,YAGEO; Manuf_Part_1: RC0603FR-07100KL; Ordered by: Subcon; ECCN_US/EU: [N/A]
R34 = res1: Resistor,36K,0603,1%,YAGEO; Ordered by: Subcon; ECCN_US/EU: NA
R36 = res1: as R68 on sheet Power
R37 = res1: Resistor,1.5K,0603,1%,YAGEO; Ordered by: Subcon; ECCN_US/EU: NA
R46 R47 R51 R55 R70 = res1: as R129 on sheet PSRAM
R50 = res1: Resistor,2.2K,0603,1%,YAGEO; Ordered by: Subcon; ECCN_US/EU: NA
SB11 = SB_OFF: Solder: NO
SB13 = SB_ON: as SB12 on sheet PSRAM
SW1 = EDG-501S: Gold Plated Contacts,4PST,1x4 Switch; Manuf_1: Grayhill Inc; Ordered by: Subcon; Second Source: NDS-04-V
T2 = NPN: NPN Bipolar Transistor; Manuf_Part_1: MMBT9013; Code - JEDEC: TO-226-AA; Ordered by: Subcon; ECCN_US/EU: EAR99/NEC
U6 = STM32F10x(48pin): IC,STM32F103CBT6,LQFP-48; Ordered by: STM; ECCN_US/EU: 3A991A2/NEC; Ref St: 9175111
U7 = ST890CDR: Manuf_1: ST; Ordered by: STM
U8 U11 = SN74LVC2T45DCUT: Manuf_1: TI; Ordered by: Subcon; ECCN_US/EU: EAR99/NEC
U9 = LD3985M33R: Ultra low drop-low noise BiCMOS voltage, regulators low ESR capacitors compatible; Manuf_1: STM; Manuf_Part_2: LDK120DM33R; Ref St: 9176161; ECCN_US/EU: EAR99/NEC
U22 = USBLC6-2SC6: Manuf_1: STM
X2 = XTAL_8M_NX3225GD: Crystal 8Mhz, 8pF, -+50PPM, SMD; Manuf_1: NDK; Manuf_Part_1: NX3225GD 8MHz EXS00A-CG04874; Manuf_Part_2: NX3225GD-8.000M-STD-CRA-3; ECCN_US/EU: EAR99/NEC; NDK Ref: X3127326; Ref St: 9157029; Provided: ST; Ordered by: STM

## Sheet USB_OTG_FS.SchDoc: USB_OTG_FS
size A4; Author: P.A.; CompanyName: STMicroelectronics; Organization: Microcontrollers Division; Address1: 12, Rue Jules HOROWITZ; Address2: 38019 Grenoble; Address3: FRANCE; DocumentNumber: MB1261; Revision: B.01; SheetNumber: 8; SheetTotal: 15; Project: STM32L496G-DISCO
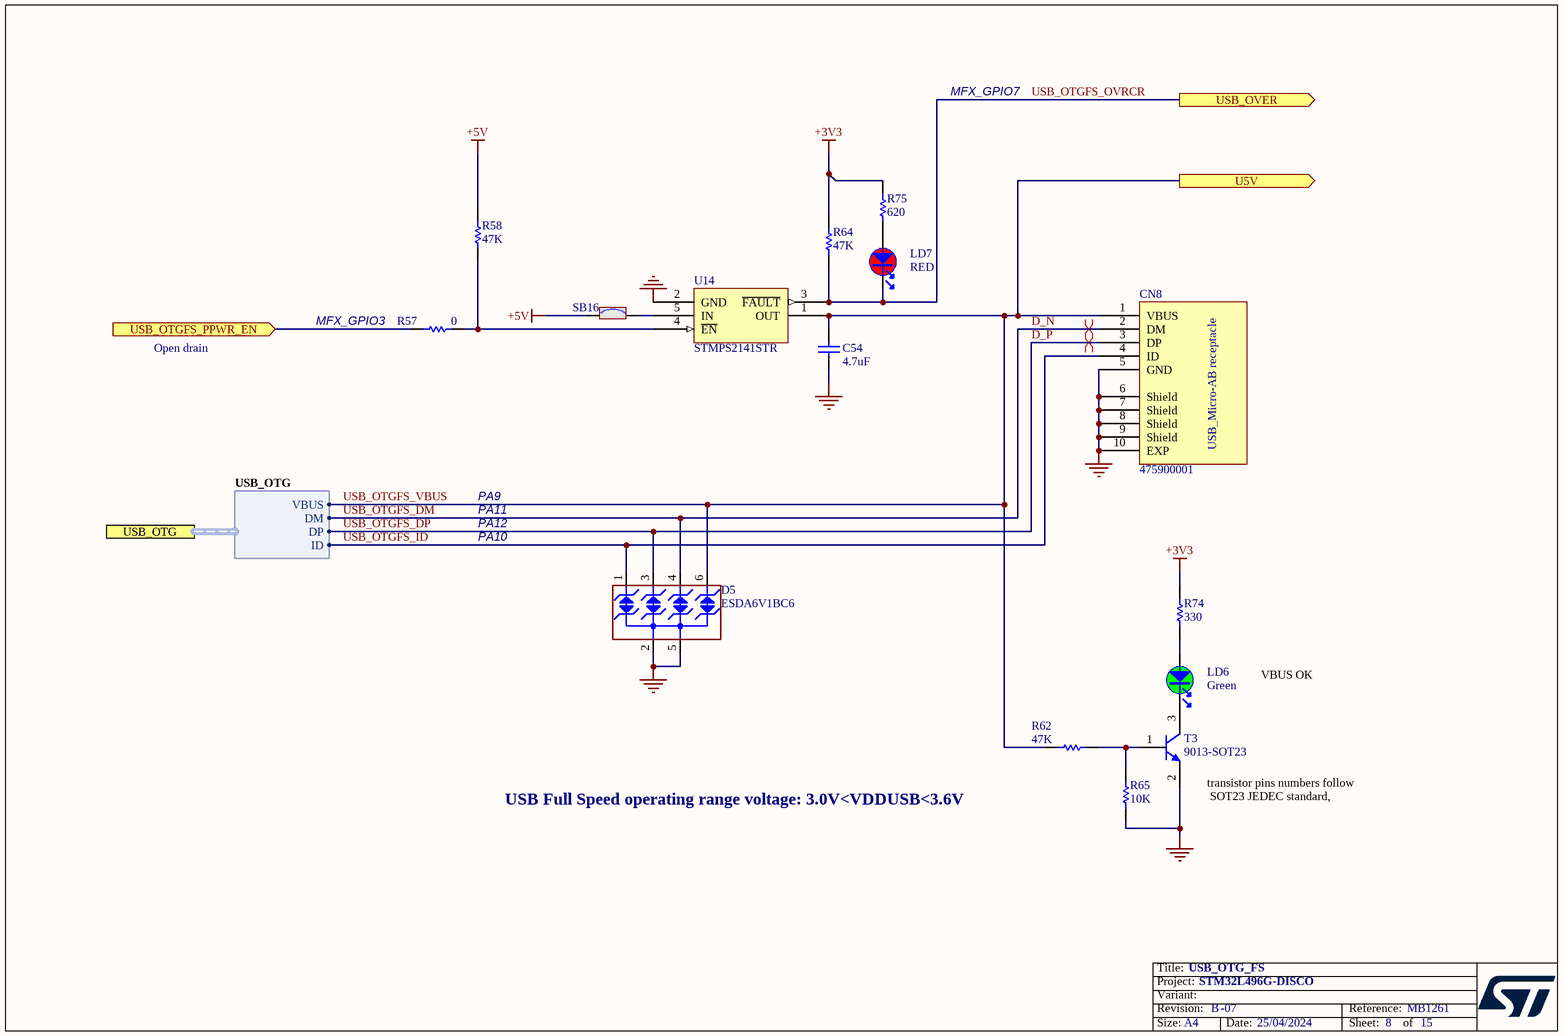
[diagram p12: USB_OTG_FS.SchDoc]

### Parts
C54  value 4.7uF  [0603C]  (hidden comment: CC0603KRX5R7BB475)
CN8  475900001  [MOLEX_47590001]
D5  ESDA6V1BC6  [SOT23-6L]
LD6  value Green  [LED_0603_OSRAM_LG-Q396-PS-35_GREEN_1A2K_H0P4]  (hidden comment: 19-213SY6C/S530-E2/TR8LED)
LD7  value RED  [LED_0603_VISHAY_VLMS1300-GS08_RED_1A2K_H0P8]  (hidden comment: 19-217/R6C-AL1M2VY/3T)
R57  value 0  [0603R]  (hidden comment: RC0603JR-070RL)
R58  value 47K  [0603R]  (hidden comment: RC0603JR-0747KL)
R62  value 47K  [0603R]  (hidden comment: RC0603JR-0747KL)
R64  value 47K  [0603R]  (hidden comment: RC0603JR-0747KL)
R65  value 10K  [0603R]  (hidden comment: RC0603JR-0710KL)
R74  value 330  [0603R]  (hidden comment: RC0603JR-07330RL)
R75  value 620  [0603R]  (hidden comment: RC0603JR-07620RL)
SB16  Solder Bridge ON  [SB_0603]  (value not drawn)
T3  9013-SOT23  [SOT-23]
U14  STMPS2141STR  [SOT23-5]

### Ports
U5V (out), USB_OTG (harness USB_OTG), USB_OTGFS_PPWR_EN (in), USB_OVER (out)

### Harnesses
USB_OTG: VBUS, DM, DP, ID

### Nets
+3V3: R64.1 R74.1 R75.1  [project net 3V3_OUT]
+5V: R58.1 SB16.1
GND: C54.2 CN8.5(GND) CN8.6(Shield) CN8.7(Shield) CN8.8(Shield) CN8.9(Shield) CN8.10(EXP) D5.2(IO2) D5.5(IO4) R65.1 T3.2(E) U14.2(GND)
D_N: CN8.2(DM) D5.4(IO3) ; port USB_OTG.DM  [also labelled USB_OTGFS_DM]
D_P: CN8.3(DP) D5.3(GND) ; port USB_OTG.DP  [also labelled USB_OTGFS_DP]
USB_OTGFS_ID: CN8.4(ID) D5.1(IO1) ; port USB_OTG.ID
USB_OTGFS_OVRCR: LD7.2 R64.2 U14.3(~{FAULT}) ; port USB_OVER
USB_OTGFS_VBUS: C54.1 CN8.1(VBUS) D5.6(NC) R62.1 U14.1(OUT) ; port U5V, port USB_OTG.VBUS
NetLD6_1: LD6.1 R74.2
NetLD6_2: LD6.2 T3.3(C)
NetLD7_1: LD7.1 R75.2
NetR57_1: R57.1 R58.2 U14.4(~{EN})
NetR57_2: R57.2 ; port USB_OTGFS_PPWR_EN
NetR62_2: R62.2 R65.2 T3.1(B)
NetSB16_2: SB16.2 U14.5(IN)

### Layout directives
differential pair: D_N, D_P

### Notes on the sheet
- MFX_GPIO7
- Open drain
- (near R57) MFX_GPIO3
- PA9
- PA11
- PA10
- PA12
- VBUS OK
- USB Full Speed operating range voltage: 3.0V<VDDUSB<3.6V
- (near T3) transistor pins numbers follow
  SOT23 JEDEC standard,

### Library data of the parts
C54 = Cap: Capacitor,4.7uF,16V, X5R,10%,0603; Manuf_1: YAGEO; Ordered by: Subcon
CN8 = 475900001: Manuf_1: MOLEX; Ordered by: Subcon; Silkscreen: USB_USER; ECCN_US/EU: NA
D5 = ESDA6V1BC6: 4-line ESD protection; Manuf_1: STM; Manuf_Part_1: ESDA5V3L; Ref St: 9179034; Provided: ST; ECCN_US/EU: EAR99/NEC
LD6 = MCD-02901: as LD2 on sheet Peripherals
LD7 = MCD-02787: as LD4 on sheet ST_LINK_V2-1_2
R57 = res1: as R129 on sheet PSRAM
R58 R62 R64 = res1: Resistor, 47K,0603,1%,YAGEO; Ordered by: Subcon; ECCN_US/EU: NA
R65 = res1: Resistor, 10K,0603,1%,YAGEO; Ordered by: Subcon; ECCN_US/EU: NA
R74 = res1: Resistor, 330R , 0603,1%,YAGEO; Ordered by: Subcon; ECCN_US/EU: NA
R75 = res1: Resistor, 620R , 0603,1%,YAGEO; Ordered by: Subcon; ECCN_US/EU: NA
SB16 = SB_ON: as SB12 on sheet PSRAM
T3 = NPN: as T2 on sheet ST_LINK_V2-1_2
U14 = STMPS2141STR: Enhanced single channel power switches; Provided: ST; ECCN_US/EU: EAR99/NEC; Ref St: 9159003; Ordered by: STM

## Sheet STMOD+.SchDoc: STMOD+ Interface
size A4; Author: P.A.; CompanyName: STMicroelectronics; Organization: Microcontrollers Division; Address1: 12, Rue Jules HOROWITZ; Address2: 38019 Grenoble; Address3: FRANCE; DocumentNumber: MB1261; Revision: B.01; SheetNumber: 14; SheetTotal: 15; Project: STM32L496G-DISCO
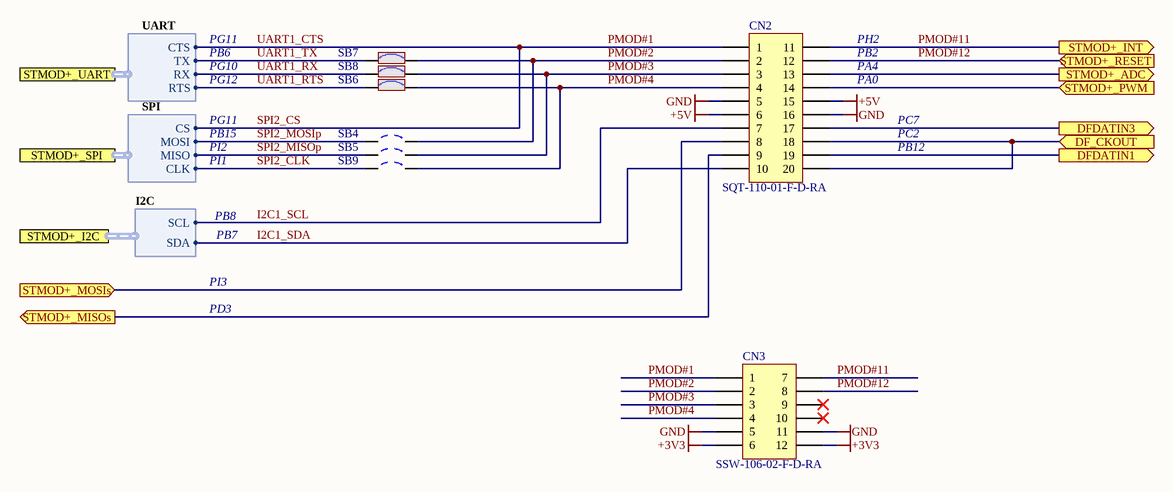
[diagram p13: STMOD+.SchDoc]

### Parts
CN2  SQT-110-01-F-D-RA  [SQT-110-01-F-D-RA]
CN3  SSW-106-02-F-D-RA  [SSW-106-02-F-D-RA]
SB4  Solder Bridge OFF  [SB_0603]  (value not drawn)
SB5  Solder Bridge OFF  [SB_0603]  (value not drawn)
SB6  Solder Bridge ON  [SB_0603]  (value not drawn)
SB7  Solder Bridge ON  [SB_0603]  (value not drawn)
SB8  Solder Bridge ON  [SB_0603]  (value not drawn)
SB9  Solder Bridge OFF  [SB_0603]  (value not drawn)

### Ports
DF_CKOUT (in), DFDATIN1 (out), DFDATIN3 (out), STMOD+_ADC (out), STMOD+_I2C (harness I2C), STMOD+_INT (out), STMOD+_MISOs (out), STMOD+_MOSIs (in), STMOD+_PWM (in), STMOD+_RESET (in), STMOD+_SPI (harness SPI), STMOD+_UART (harness UART)

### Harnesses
UART: RX, TX, RTS, CTS
SPI: MISO, MOSI, CLK, CS
I2C: SDA, SCL

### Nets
+3V3: CN3.6 CN3.12  [project net 3V3_OUT]
+5V: CN2.6 CN2.15
GND: CN2.5 CN2.16 CN3.5 CN3.11
CKOUT: CN2.18 CN2.20 ; port DF_CKOUT
DATIN3: CN2.17 ; port DFDATIN3
DFDATIN1: CN2.19 ; port DFDATIN1
I2C1_SCL: CN2.7 ; port STMOD+_I2C.SCL  [project net ARD_D15]
I2C1_SDA: CN2.10 ; port STMOD+_I2C.SDA  [project net ARD_D14]
PMOD#1: CN2.1 CN3.1 ; port STMOD+_UART.CTS, port STMOD+_SPI.CS  [also labelled SPI2_CS, UART1_CTS]
PMOD#2: CN2.2 CN3.2 SB4.2 SB7.2
PMOD#3: CN2.3 CN3.3 SB5.2 SB8.2
PMOD#4: CN2.4 CN3.4 SB6.2 SB9.2
PMOD#11: CN2.11 CN3.7 ; port STMOD+_INT
PMOD#12: CN2.12 CN3.8 ; port STMOD+_RESET
SPI2_CLK: SB9.1 ; port STMOD+_SPI.CLK
SPI2_MISOp: SB5.1 ; port STMOD+_SPI.MISO  [project net SPI2_MISO]
SPI2_MISOs: CN2.9 ; port STMOD+_MISOs
SPI2_MOSIp: SB4.1 ; port STMOD+_SPI.MOSI  [project net SPI2_MOSI]
SPI2_MOSIs: CN2.8 ; port STMOD+_MOSIs
STMOD+_ADC: CN2.13 ; port STMOD+_ADC
STMOD+_PWM: CN2.14 ; port STMOD+_PWM
UART1_RTS: SB6.1 ; port STMOD+_UART.RTS
UART1_RX: SB8.1 ; port STMOD+_UART.RX
UART1_TX: SB7.1 ; port STMOD+_UART.TX

Not connected (* = marked no-connect by the designer): CN3 9* 10*

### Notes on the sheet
- PG11
- PH2
- PG10
- PG12
- PB6
- PA0
- PA4
- PB2
- PB15
- PI1
- PI2
- PB12
- PC2
- PC7
- PB8
- PB7
- PD3
- PI3

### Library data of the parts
CN2 = Header 10X2A: Header, 10-Pin, Dual row; Manuf_1: ATOM; Manuf_Part_1: FH200210C-12000; Ordered by: Subcon
CN3 = Header 6X2A: Header, 6-Pin, Dual row; Manuf_Part_1: FH254206C-1600; Manuf_1: ATOM; Ordered by: Subcon
SB4 SB5 SB9 = SB_OFF: Solder: NO
SB6-SB8 = SB_ON: as SB12 on sheet PSRAM

## Sheet Audio.SchDoc: Audio&DFSDM
size A4; Author: P.A.; CompanyName: STMicroelectronics; Organization: Microcontrollers Division; Address1: 12, Rue Jules HOROWITZ; Address2: 38019 Grenoble; Address3: FRANCE; DocumentNumber: MB1261; Revision: B.01; SheetNumber: 15; SheetTotal: 15; Project: STM32L496G-DISCO
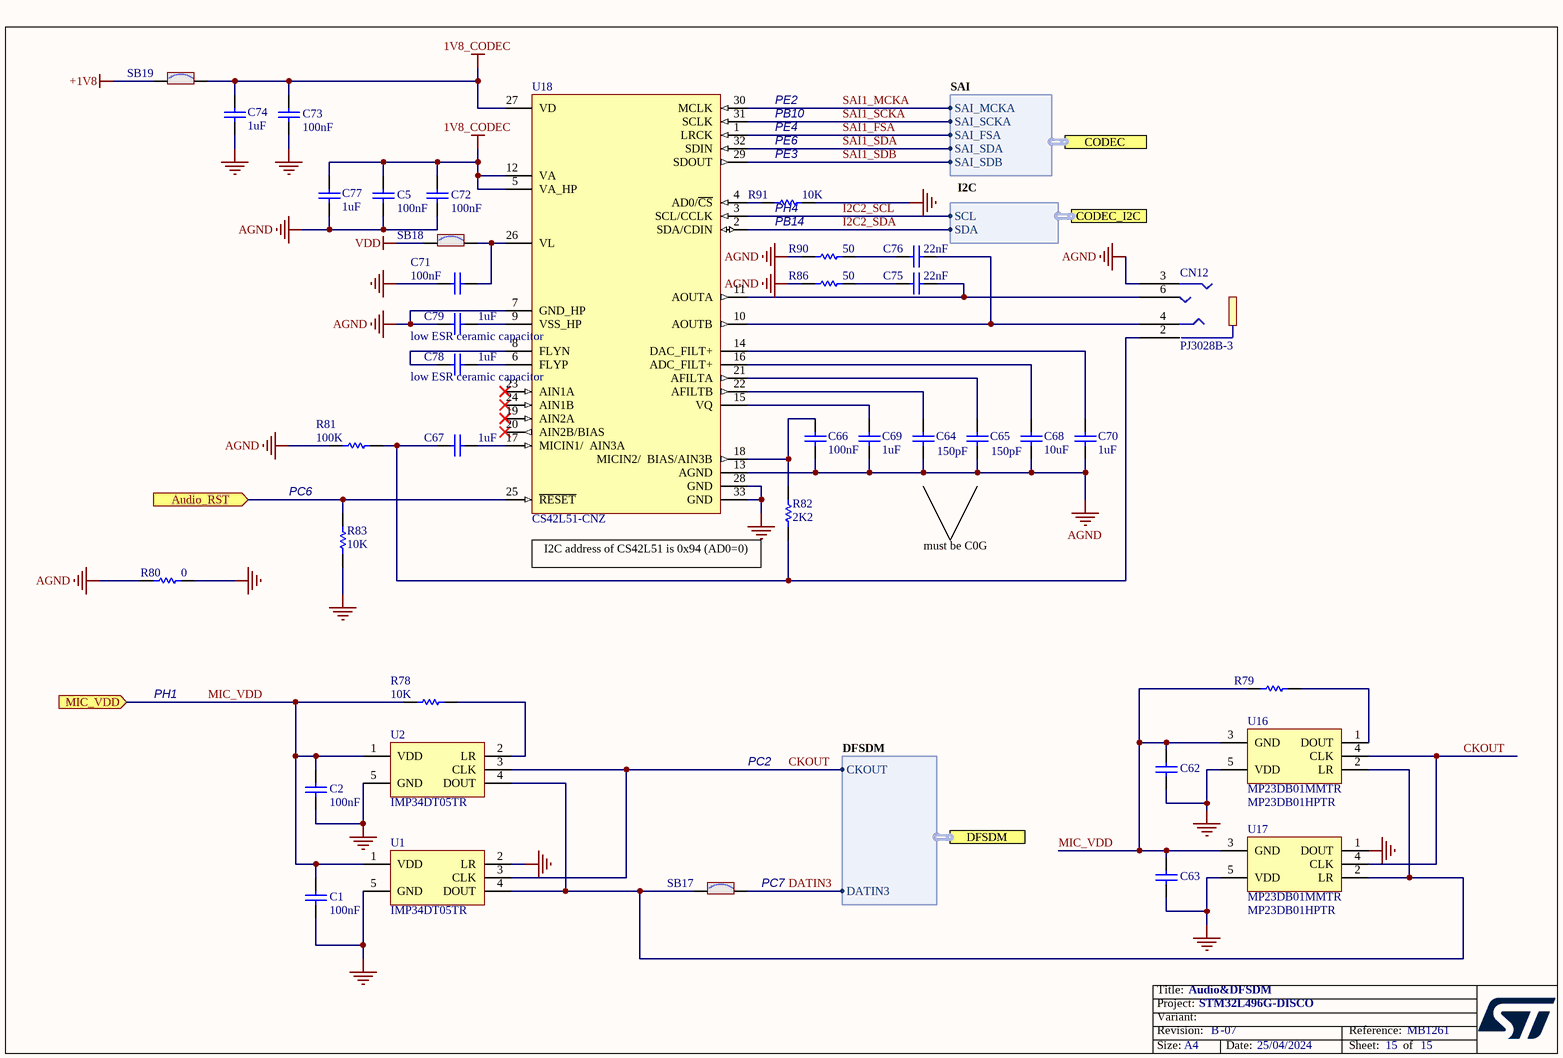
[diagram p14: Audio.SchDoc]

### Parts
C1  value 100nF  [0603C]  (hidden comment: CC0603KRX7R7BB104)
C2  value 100nF  [0603C]  (hidden comment: CC0603KRX7R7BB104)
C5  value 100nF  [0603C]  (hidden comment: CC0603KRX7R7BB104)
C62  (no value)  [0603C]
C63  (no value)  [0603C]
C64  value 150pF  [0603C]  (hidden comment: CC0603JRNPO9BN151)
C65  value 150pF  [0603C]  (hidden comment: CC0603JRNPO9BN151)
C66  value 100nF  [0603C]  (hidden comment: CC0603KRX7R7BB104)
C67  value 1uF  [0603C]  (hidden comment: CC0603KRX5R7BB105)
C68  value 10uF  [0603C]  (hidden comment: C1608X5R1A106K080AC)
C69  value 1uF  [0603C]  (hidden comment: CC0603KRX5R7BB105)
C70  value 1uF  [0603C]  (hidden comment: CC0603KRX5R7BB105)
C71  value 100nF  [0603C]  (hidden comment: CC0603KRX7R7BB104)
C72  value 100nF  [0603C]  (hidden comment: CC0603KRX7R7BB104)
C73  value 100nF  [0603C]  (hidden comment: CC0603KRX7R7BB104)
C74  value 1uF  [0603C]  (hidden comment: CC0603KRX5R7BB105)
C75  value 22nF  [0603C]  (hidden comment: CC0603KRX7R8BB223)
C76  value 22nF  [0603C]  (hidden comment: CC0603KRX7R8BB223)
C77  value 1uF  [0603C]  (hidden comment: CC0603KRX5R7BB105)
C78  value 1uF  [0603C]  (hidden comment: CC0603KRX5R7BB105)
C79  value 1uF  [0603C]  (hidden comment: CC0603KRX5R7BB105)
CN12  PJ3028B-3  [PJ3028B]
R78  value 10K  [0603R]  (hidden comment: RC0603FR-0710KL)
R79  (no value)  [0603R]
R80  value 0  [0603R]  (hidden comment: RC0603JR-070RL)
R81  value 100K  [0603R]  (hidden comment: RC0603FR-07100KL)
R82  value 2K2  [0603R]  (hidden comment: RC0603FR-072K2L)
R83  value 10K  [0603R]  (hidden comment: RC0603FR-0710KL)
R86  value 50  [0603R]  (hidden comment: RC0603FR-0750RL)
R90  value 50  [0603R]  (hidden comment: RC0603FR-0750RL)
R91  value 10K  [0603R]  (hidden comment: RC0603FR-0710KL)
SB17  Solder Bridge ON  [SB_0603]  (value not drawn)
SB18  Solder Bridge ON  [SB_0603]  (value not drawn)
SB19  Solder Bridge ON  [SB_0603]  (value not drawn)
U1  IMP34DT05TR  [MIC_HCLGA_3X4X1_4LD]
U2  IMP34DT05TR  [MIC_HCLGA_3X4X1_4LD]
U16  MP23DB01MMTR  value MP23DB01HPTR  [MIC_STM_MP23DB01MMTR]
U17  MP23DB01MMTR  value MP23DB01HPTR  [MIC_STM_MP23DB01MMTR]
U18  CS42L51-CNZ  [QFN32_0R5_5X5]

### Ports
Audio_RST (in), CODEC (harness SAI), CODEC_I2C (harness I2C), DFSDM (harness DFSDM), MIC_VDD (in)

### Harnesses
SAI: SAI_SDB, SAI_FSA, SAI_MCKA, SAI_SDA, SAI_SCKA
I2C: SDA, SCL
DFSDM: DATIN3, CKOUT

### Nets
1V8_CODEC: C5.1 C72.1 C73.1 C74.1 C77.1 SB19.2 U18.5(VA_HP) U18.12(VA) U18.27(VD)
+1V8: SB19.1  [project net 1V8_OUT]
AGND: C5.2 C64.2 C65.2 C66.1 C68.1 C69.1 C70.1 C72.2 C77.2 C79.1 CN12.3 R80.2 R81.2 R86.2 R90.2 U18.7(GND_HP) U18.13(AGND)
GND: C1.2 C2.2 C62.2 C63.2 C71.1 C73.2 C74.2 R80.1 R83.1 R91.1 U1.2(LR) U1.5(GND) U2.5(GND) U16.5(VDD) U17.1(DOUT) U17.5(VDD) U18.28(GND) U18.33(GND)
VDD: SB18.1
Audio_RST: R83.2 U18.25(~{RESET}) ; port Audio_RST
CKOUT: U1.3(CLK) U2.3(CLK) U16.4(CLK) U17.4(CLK) ; port DFSDM.CKOUT
DATIN3: SB17.2 ; port DFSDM.DATIN3
I2C2_SCL: U18.3(SCL/CCLK) ; port CODEC_I2C.SCL
I2C2_SDA: U18.2(SDA/CDIN) ; port CODEC_I2C.SDA
MIC_VDD: C1.1 C2.1 C62.1 C63.1 R78.2 R79.2 U1.1(VDD) U2.1(VDD) U16.3(GND) U17.3(GND) ; port MIC_VDD
SAI1_FSA: U18.1(LRCK) ; port CODEC.SAI_FSA
SAI1_MCKA: U18.30(MCLK) ; port CODEC.SAI_MCKA
SAI1_SCKA: U18.31(SCLK) ; port CODEC.SAI_SCKA
SAI1_SDA: U18.32(SDIN) ; port CODEC.SAI_SDA
SAI1_SDB: U18.29(SDOUT) ; port CODEC.SAI_SDB
NetC64_1: C64.1 U18.22(AFILTB)
NetC65_1: C65.1 U18.21(AFILTA)
NetC66_2: C66.2 R82.2 U18.18(MICIN2/__BIAS/AIN3B)
NetC67_1: C67.1 CN12.2 R81.1 R82.1
NetC67_2: C67.2 U18.17(MICIN1/__AIN3A)
NetC68_2: C68.2 U18.16(ADC_FILT+)
NetC69_2: C69.2 U18.15(VQ)
NetC70_2: C70.2 U18.14(DAC_FILT+)
NetC71_2: C71.2 SB18.2 U18.26(VL)
NetC75_1: C75.1 CN12.6 U18.11(AOUTA)
NetC75_2: C75.2 R86.1
NetC76_1: C76.1 CN12.4 U18.10(AOUTB)
NetC76_2: C76.2 R90.1
NetC78_1: C78.1 U18.8(FLYN)
NetC78_2: C78.2 U18.6(FLYP)
NetC79_2: C79.2 U18.9(VSS_HP)
NetR78_1: R78.1 U2.2(LR)
NetR79_1: R79.1 U16.1(DOUT)
NetR91_2: R91.2 U18.4(AD0/~{CS})
NetSB17_1: SB17.1 U1.4(DOUT) U2.4(DOUT) U16.2(LR) U17.2(LR)

Not connected (* = marked no-connect by the designer): U18 19(AIN2A)* 20(AIN2B/BIAS)* 23(AIN1A)* 24(AIN1B)*

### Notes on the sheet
- PB10
- PE2
- PE4
- PE6
- PE3
- (near R91) PH4
- (near R91) PB14
- (near U18) low ESR ceramic capacitor
- PC6
- I2C address of CS42L51 is 0x94 (AD0=0)
- must be C0G
- PH1
- PC2
- (near SB17) PC7

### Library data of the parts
C1 C2 C5 C66 C71-C73 = Cap: as C15 on sheet PSRAM
C62 C63 = Cap: Capacitor,100nF,10%,16V,X7R,0603,YAGEO; Manuf_Part_1: CC0603KRX7R7BB104; Ordered by: Subcon
C64 C65 = Cap: Capacitor,150pF,0603,50V,5%,NPO; Manuf_1: YAGEO; Ordered by: Subcon; ECCN_US/EU: NA
C67 C69 C70 C74 C77-C79 = Cap: as C19 on sheet ST_LINK_V2-1_2
C68 = Cap: Capacitor,10uF,10%,10V,X5R,0603,C1608X5R1A106K080AC; Manuf_1: TDK; Manuf_Part_1: C1608X5R1A106KT000E; Ordered by: Subcon; ECCN_US/EU: NA
C75 C76 = Cap: Capacitor,22nF,10%,25V,X7R,0603; Manuf_1: YAGEO; Ordered by: Subcon; ECCN_US/EU: NA
CN12 = PJ3028B-3: Manuf_1: QIAOD; Ordered by: Subcon; Silkscreen: AUDIO_JACK; ECCN_US/EU: NA
R78 R83 R91 = res1: as R27 on sheet QSPI
R79 = res1: Resistor,10K,0603,1%,YAGEO; Manuf_Part_1: RC0603FR-0710KL; Ordered by: Subcon; ECCN_US/EU: [N/A]
R80 = res1: as R129 on sheet PSRAM
R81 = res1: as R13-R15 on sheet PSRAM
R82 = res1: as R50 on sheet ST_LINK_V2-1_2
R86 R90 = res1: Resistor,50R,0603,1%,YAGEO; Ordered by: Subcon; ECCN_US/EU: NA
SB17-SB19 = SB_ON: as SB12 on sheet PSRAM
U1 U2 = MCD-01715: MEMS audio sensor omnidirectional digital microphone for industrial applications; BMS_Part_Number: 9177995; Part_Type: IC; Part_Preference: Recommended; Manufacturer: STMICROELECTRONICS; Manufacturer_HQ_COO: EU; Component_Country_Of_Origin: Philippines
U16 U17 = MCD-02122: MEMS, Audio sensor Multi performance mode digital microphone; Part_Type: IC; Part_Preference: Recommended; Manufacturer: STMICROELECTRONICS; Manufacturer_HQ_COO: EU; Component_Country_Of_Origin: China; ShowFields: YES; ID: 4222
U18 = CS42L51-CNZ: Low-Power, Stereo Codec with Headphone Amp; Manuf_1: Cirrus; Ordered by: Subcon

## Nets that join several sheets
1V8_OUT: Power (5 pins), Audio (SB19.1)
3V3_LCD: LCD (8 pins), PSRAM (R130.2)
3V3_OUT: Arduino_ Connectors (CN15.4 R123.1), LCD (R77.2 T12.4), MCU (JP4.1), Peripherals (LD1.1 LD2.1), Power (5 pins), USB_OTG_FS (R64.1 R74.1 R75.1), STMOD+ (CN3.6 CN3.12)
5V_USB_CHARGER: Power (JP7.9), ST_LINK_V2-1_2 (10 pins)
+5V: IDD_measurement (R116.2 T10.4), LCD (L5.1 R115.1), Power (23 pins), ST_LINK_V2-1_2 (SW1.6), USB_OTG_FS (R58.1 SB16.1), STMOD+ (CN2.6 CN2.15)
ARD_5V: Arduino_ Connectors (CN15.5), Power (JP3.2)
E5V: Arduino_ Connectors (R72.1), Power (C37.1 JP7.3 U10.2 U10.4), ST_LINK_V2-1_2 (D2.1)
GND: Top (H1.1 H2.1 H3.1 H4.1), Arduino_ Connectors (6 pins), Camera (7 pins), IDD_measurement (25 pins), LCD (15 pins), MCU (39 pins), Peripherals (B1.2 B1.3 CN17.6 CN17.9), Power (16 pins), PSRAM (C15.2 C16.2 U4.D1 U4.E6), QSPI (C4.2 U3.4), ST_LINK_V2-1_2 (51 pins), USB_OTG_FS (12 pins), STMOD+ (CN2.5 CN2.16 CN3.5 CN3.11), Audio (18 pins)
U5V_ST_LINK: Power (JP7.1), ST_LINK_V2-1_2 (C29.2 U7.6 U7.7)
VDD: Arduino_ Connectors (CN15.2), Camera (C60.1 C61.1 CN1.20 CN1.30), IDD_measurement (R94.2 R114.1 T8.4), LCD (T11.4), MCU (R21.1 R42.1 R43.1), Peripherals (7 pins), Power (JP5.2), QSPI (R27.2 SB3.1), ST_LINK_V2-1_2 (CN4.1 SW1.5), Audio (SB18.1)
VDD_LCD: LCD (13 pins), PSRAM (R129.2)
VDD_MCU: IDD_measurement (JP2.2 SB24.1), MCU (29 pins)
VIN: Arduino_ Connectors (CN15.8), Power (C45.1 U10.3)
VREF+: Arduino_ Connectors (C3.1 SB2.2), MCU (C13.1 C14.1 R18.1 U5.L1)
ARD_A0: Arduino_ Connectors (CN16.1), MCU (U5.H5)
ARD_A1: Arduino_ Connectors (CN16.2), MCU (U5.J3)
ARD_A2: Arduino_ Connectors (CN16.3), MCU (U5.K1)
ARD_A3: Arduino_ Connectors (CN16.4), MCU (U5.H4)
ARD_A4: Arduino_ Connectors (SB26.1), MCU (U5.N2)
ARD_A5: Arduino_ Connectors (SB28.1), MCU (U5.J2)
ARD_D0: Arduino_ Connectors (CN11.1), MCU (U5.H9)
ARD_D1: Arduino_ Connectors (CN11.2), MCU (U5.H10)
ARD_D2: Arduino_ Connectors (CN11.3), MCU (U5.G7)
ARD_D3: Arduino_ Connectors (CN11.4), MCU (U5.B12)
ARD_D4: Arduino_ Connectors (CN11.5), MCU (U5.C3)
ARD_D5: Arduino_ Connectors (CN11.6), MCU (U5.D4)
ARD_D6: Arduino_ Connectors (CN11.7), MCU (U5.B9)
ARD_D7: Arduino_ Connectors (CN11.8), MCU (U5.G11)
ARD_D8: Arduino_ Connectors (CN10.1), MCU (U5.C6)
ARD_D9: Arduino_ Connectors (CN10.2), MCU (U5.C9)
ARD_D10: Arduino_ Connectors (CN10.3), MCU (U5.A9)
ARD_D11: Arduino_ Connectors (CN10.4), MCU (U5.B5)
ARD_D12: Arduino_ Connectors (CN10.5), MCU (U5.A5)
ARD_D13: Arduino_ Connectors (CN10.6 SB1.2), MCU (U5.K4)
ARD_D14: Arduino_ Connectors (CN10.9 SB25.1), MCU (U5.D5), STMOD+ (CN2.10)
ARD_D15: Arduino_ Connectors (CN10.10 SB27.1), MCU (U5.C4), STMOD+ (CN2.7)
Audio_RST: MCU (U5.F11), Audio (R83.2 U18.25)
CKOUT: MCU (U5.J4), STMOD+ (CN2.18 CN2.20), Audio (U1.3 U2.3 U16.4 U17.4)
CTP_INT: LCD (CN13.2 R89.1), MCU (U5.G6)
D0: LCD (CN6.18), MCU (U5.K10), PSRAM (U4.B6)
D1: LCD (CN6.17), MCU (U5.H11), PSRAM (U4.C5)
D2: LCD (CN6.16), MCU (U5.B8), PSRAM (U4.C6)
D3: LCD (CN6.15), MCU (U5.C8), PSRAM (U4.D5)
D4: LCD (CN6.14), MCU (U5.L7), PSRAM (U4.E5)
D5: LCD (CN6.13), MCU (U5.K7), PSRAM (U4.F5)
D6: LCD (CN6.12), MCU (U5.J7), PSRAM (U4.F6)
D7: LCD (CN6.11), MCU (U5.H7), PSRAM (U4.G6)
D8: LCD (CN6.10), MCU (U5.N8), PSRAM (U4.B1)
D9: LCD (CN6.9), MCU (U5.M8), PSRAM (U4.C1)
D10: LCD (CN6.8), MCU (U5.L8), PSRAM (U4.C2)
D11: LCD (CN6.7), MCU (U5.K8), PSRAM (U4.D2)
D12: LCD (CN6.6), MCU (U5.J8), PSRAM (U4.E2)
D13: LCD (CN6.5), MCU (U5.L11), PSRAM (U4.F2)
D14: LCD (CN6.4), MCU (U5.L10), PSRAM (U4.F1)
D15: LCD (CN6.3), MCU (U5.J13), PSRAM (U4.G1)
D_N: MCU (U5.E13), USB_OTG_FS (CN8.2 D5.4)
D_P: MCU (U5.D13), USB_OTG_FS (CN8.3 D5.3)
DATIN3: MCU (U5.G12), STMOD+ (CN2.17), Audio (SB17.2)
DCMI_CLK: Camera (R100.2), MCU (U5.G8)
DCMI_D0: Camera (CN1.4), MCU (U5.D11)
DCMI_D1: Camera (CN1.5), MCU (U5.M9)
DCMI_D2: Camera (CN1.6), MCU (U5.M10)
DCMI_D3: Camera (CN1.7), MCU (U5.B13)
DCMI_D4: Camera (CN1.8), MCU (U5.A13)
DCMI_D5: Camera (CN1.9), MCU (U5.D10)
DCMI_D6: Camera (CN1.10), MCU (U5.E4)
DCMI_D7: Camera (CN1.11), MCU (U5.B2)
DCMI_HSYNC: Camera (CN1.17), MCU (U5.N10)
DCMI_PIXCK: Camera (CN1.15), MCU (U5.L9)
DCMI_PWR_EN: Camera (CN1.25), IDD_measurement (U21.16)
DCMI_VSYNC: Camera (CN1.19), MCU (U5.E10)
DFDATIN1: MCU (U5.N12), STMOD+ (CN2.19)
I2C2_SCL: IDD_measurement (U21.42), MCU (R42.2 U5.K9)
I2C2_SDA: IDD_measurement (U21.43), MCU (R43.2 U5.M13)
JOY_DOWN: MCU (U5.A1), Peripherals (B2.3)
JOY_LEFT: MCU (U5.B1), Peripherals (B2.1)
JOY_RIGHT: MCU (U5.M5), Peripherals (B2.4)
JOY_SEL: MCU (U5.E1), Peripherals (B2.2)
JOY_UP: MCU (U5.C11), Peripherals (B2.6)
LCD_BL: LCD (R76.1 R77.1 U15.7), MCU (U5.A12)
LCD_NE: LCD (CN6.22 R52.1), MCU (U5.F7)
LCD_OE: LCD (CN6.19), MCU (U5.C7), PSRAM (U4.A2)
LCD_PWR_ON: LCD (R115.2 T11.3 T12.3), MCU (U5.H1)
LCD_RS: LCD (CN6.21), MCU (U5.K13), PSRAM (U4.H1)
LCD_RST: IDD_measurement (U21.20), LCD (CN6.23 R117.2)
LCD_TE: LCD (CN6.2), MCU (U5.D12)
LCD_WE: LCD (CN6.20), MCU (U5.D7), PSRAM (U4.G5)
LED1: MCU (U5.N13), Peripherals (R2.1)
MFX_IRQ_OUT: IDD_measurement (U21.46), MCU (U5.J5)
MFX_WAKEUP: IDD_measurement (R109.2 U21.2), MCU (U5.E11)
MIC_VDD: MCU (U5.J1), Audio (10 pins)
NetCN13_7: IDD_measurement (U21.19), LCD (CN13.7 R99.1 R104.1)
NetR1_1: IDD_measurement (U21.40), Peripherals (R1.1)
NRST: Arduino_ Connectors (CN15.3), IDD_measurement (D6.2), ST_LINK_V2-1_2 (R25.2 SW1.7)
NRST: MCU (C10.1 U5.H3), Peripherals (B1.1 B1.4)
PMOD#1: MCU (U5.E6), STMOD+ (CN2.1 CN3.1)
PMOD#11: MCU (U5.A2), STMOD+ (CN2.11 CN3.7)
PMOD#12: MCU (U5.N5), STMOD+ (CN2.12 CN3.8)
PSRAM_A0: MCU (U5.F5), PSRAM (U4.A3)
PSRAM_A1: MCU (U5.F4), PSRAM (U4.A4)
PSRAM_A2: MCU (U5.F3), PSRAM (U4.A5)
PSRAM_A3: MCU (U5.G3), PSRAM (U4.B3)
PSRAM_A4: MCU (U5.G4), PSRAM (U4.B4)
PSRAM_A5: MCU (U5.G5), PSRAM (U4.C3)
PSRAM_A6: MCU (U5.N6), PSRAM (U4.C4)
PSRAM_A7: MCU (U5.M6), PSRAM (U4.D4)
PSRAM_A8: MCU (U5.L6), PSRAM (U4.H2)
PSRAM_A9: MCU (U5.K6), PSRAM (U4.H3)
PSRAM_A10: MCU (U5.J6), PSRAM (U4.H4)
PSRAM_A11: MCU (U5.H6), PSRAM (U4.H5)
PSRAM_A12: MCU (U5.J12), PSRAM (U4.G3)
PSRAM_A13: MCU (U5.J11), PSRAM (U4.G4)
PSRAM_A14: MCU (U5.J10), PSRAM (U4.F3)
PSRAM_A15: MCU (U5.J9), PSRAM (U4.F4)
PSRAM_A16: MCU (U5.K12), PSRAM (U4.E4)
PSRAM_A17: MCU (U5.K11), PSRAM (U4.D3)
PSRAM_NBL0: MCU (U5.A4), PSRAM (U4.A1)
PSRAM_NBL1: MCU (U5.B4), PSRAM (R13.1 U4.B2)
PSRAM_NE: MCU (U5.B7), PSRAM (JP9.1 R12.2)
QSPI_BK1_IO0: MCU (U5.L5), QSPI (R8.1)
QSPI_BK1_IO1: MCU (U5.K5), QSPI (R28.1)
QSPI_BK1_IO2: MCU (U5.L4), QSPI (R29.1)
QSPI_BK1_IO3: MCU (U5.M4), QSPI (R6.1)
QSPI_BK1_NCS: MCU (U5.H8), QSPI (R26.1)
QSPI_CLK: MCU (U5.M2), QSPI (R7.1)
SAI1_FSA: MCU (U5.D1), Audio (U18.1)
SAI1_MCKA: MCU (U5.D3), Audio (U18.30)
SAI1_SCKA: MCU (U5.N9), Audio (U18.31)
SAI1_SDA: MCU (U5.E3), Audio (U18.32)
SAI1_SDB: MCU (U5.D2), Audio (U18.29)
SPI2_CLK: MCU (U5.B11), STMOD+ (SB9.1)
SPI2_MISO: MCU (U5.B10), STMOD+ (SB5.1)
SPI2_MISOs: MCU (U5.E8), STMOD+ (CN2.9)
SPI2_MOSI: MCU (U5.M12), STMOD+ (SB4.1)
SPI2_MOSIs: MCU (U5.C10), STMOD+ (CN2.8)
STMOD+_ADC: MCU (U5.L3), STMOD+ (CN2.13)
STMOD+_PWM: MCU (U5.K3), STMOD+ (CN2.14)
SWCLK: MCU (U5.A10), ST_LINK_V2-1_2 (R4.2 R47.1)
SWDIO: MCU (U5.A11), ST_LINK_V2-1_2 (R5.2 SW1.8)
SWO: MCU (U5.A6), ST_LINK_V2-1_2 (R16.2 R51.1)
UART1_RTS: MCU (U5.F6), STMOD+ (SB6.1)
UART1_RX: MCU (U5.D6), STMOD+ (SB8.1)
UART1_TX: MCU (U5.C5), STMOD+ (SB7.1)
USART2_RX: MCU (U5.E7), ST_LINK_V2-1_2 (R46.2)
USART2_TX: MCU (U5.N1), ST_LINK_V2-1_2 (R55.1)
USB_OTGFS_ID: MCU (U5.F9), USB_OTG_FS (CN8.4 D5.1)
USB_OTGFS_OVRCR: IDD_measurement (U21.17), USB_OTG_FS (LD7.2 R64.2 U14.3)
USB_OTGFS_VBUS: MCU (U5.F10), Power (JP7.5), ST_LINK_V2-1_2 (D4.1), USB_OTG_FS (5 pins)
uSD_CLK: MCU (U5.F8), Peripherals (CN17.5)
uSD_CMD: MCU (U5.D8), Peripherals (CN17.3 R120.1)
uSD_D0: MCU (U5.G10), Peripherals (CN17.7 R121.1)
uSD_D1: MCU (U5.G9), Peripherals (CN17.8 R122.1)
uSD_D2: MCU (U5.D9), Peripherals (CN17.1 R118.1)
uSD_D3: MCU (U5.E9), Peripherals (CN17.2 R119.1)
uSD_Detect: IDD_measurement (U21.29), Peripherals (CN17.10)

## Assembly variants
L496G: not fitted C3 C62 C63 C99 CN4 CN9 CN14 D2 D4 JP1 JP10 R18 R21 R24 R31 R41 R77 R79 R87 R88 R89 R99 R104 R130 SB2 SB4 SB5 SB9 SB11 SB15 SB22 SB25 SB27 U16 U17 U23 U24
CELL02: not fitted C3 C62 C63 C99 CN4 CN9 CN14 D2 D4 JP1 JP10 R18 R21 R24 R31 R41 R77 R79 R87 R88 R89 R99 R104 R130 SB2 SB4 SB5 SB9 SB11 SB15 SB22 SB25 SB27 U16 U17 U23 U24 ZZ1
